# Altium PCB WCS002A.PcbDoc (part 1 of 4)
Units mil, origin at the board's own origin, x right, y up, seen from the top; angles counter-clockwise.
Board outline 2300 x 4058 mil, 4 copper layers (TOP, GND, PWR, BOTTOM), stack 28.8 mil thick; 311 components, 217 nets, 982 pads, 644 vias.
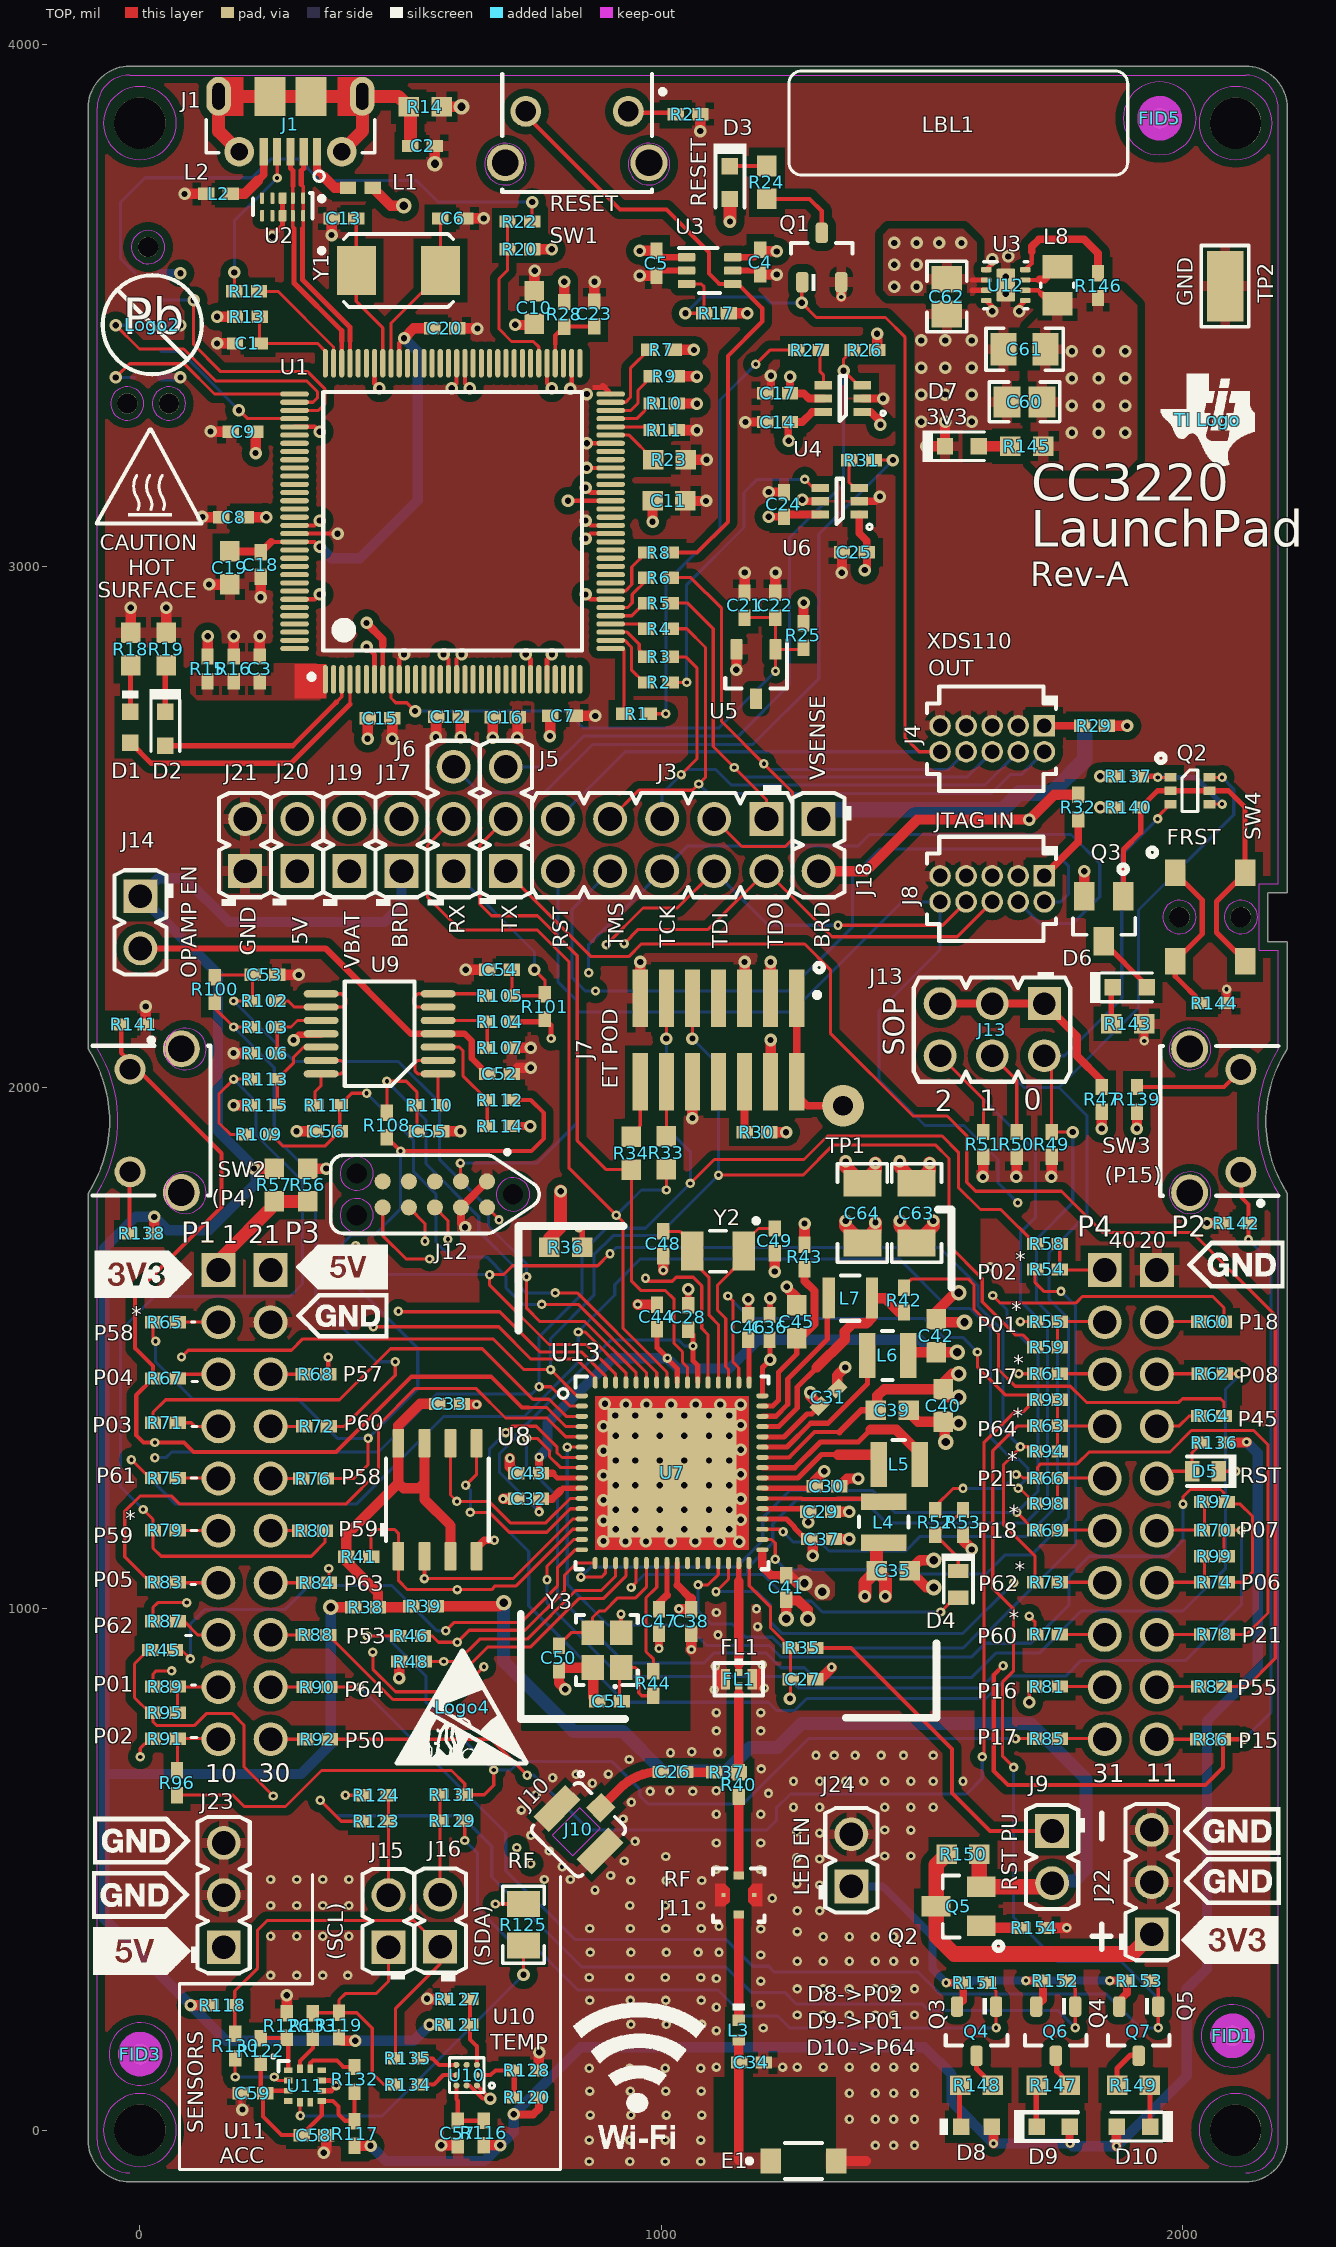
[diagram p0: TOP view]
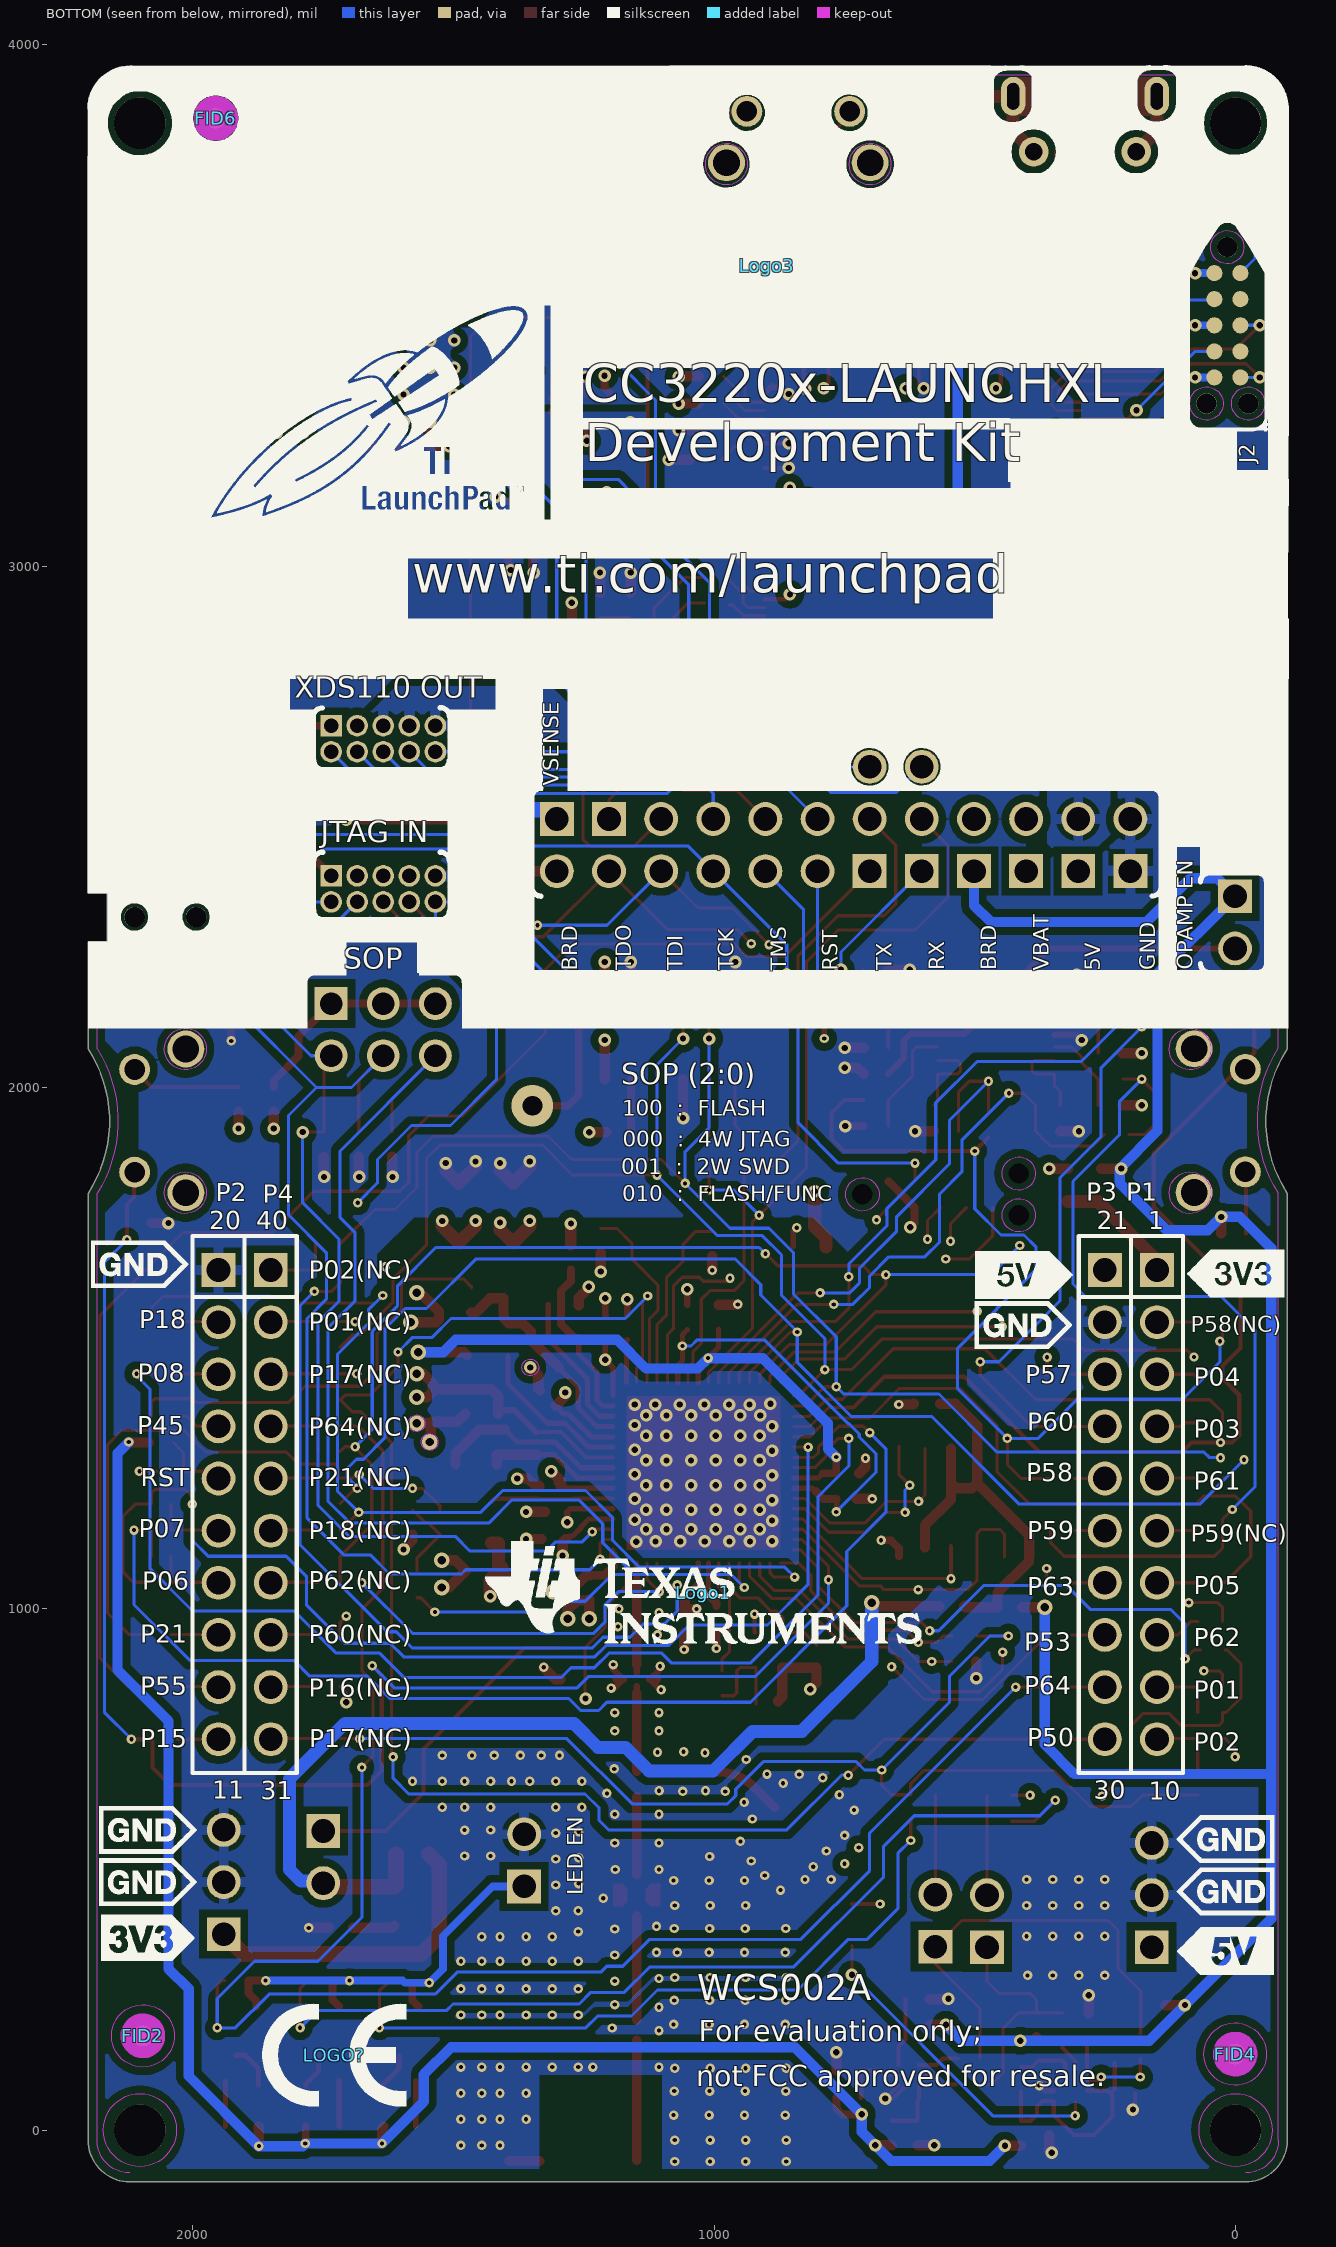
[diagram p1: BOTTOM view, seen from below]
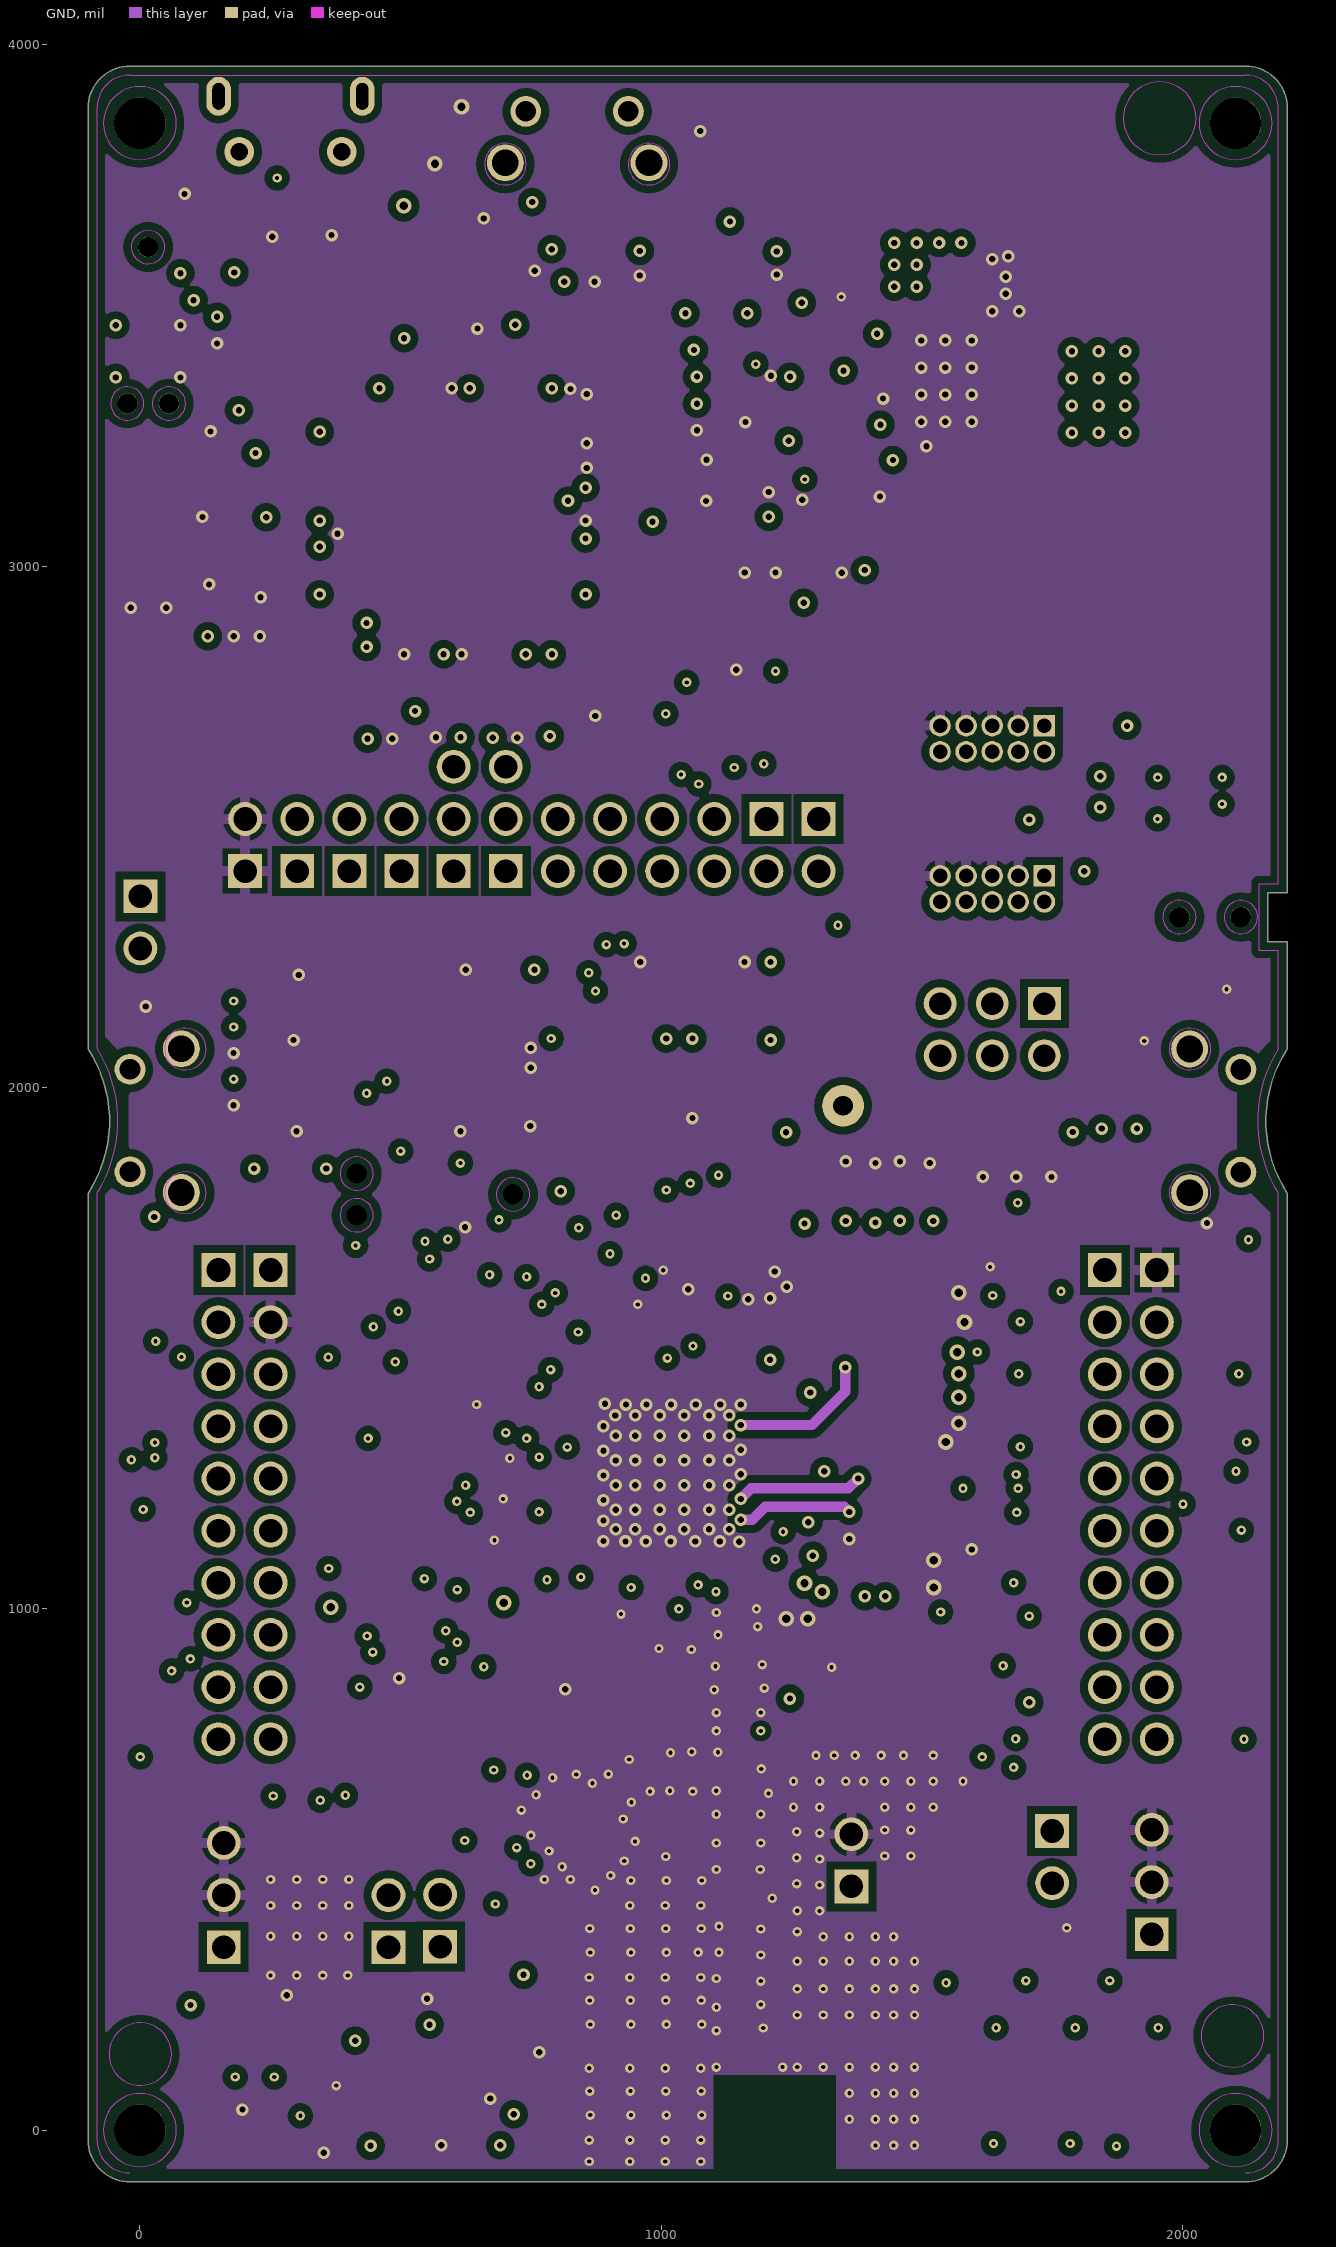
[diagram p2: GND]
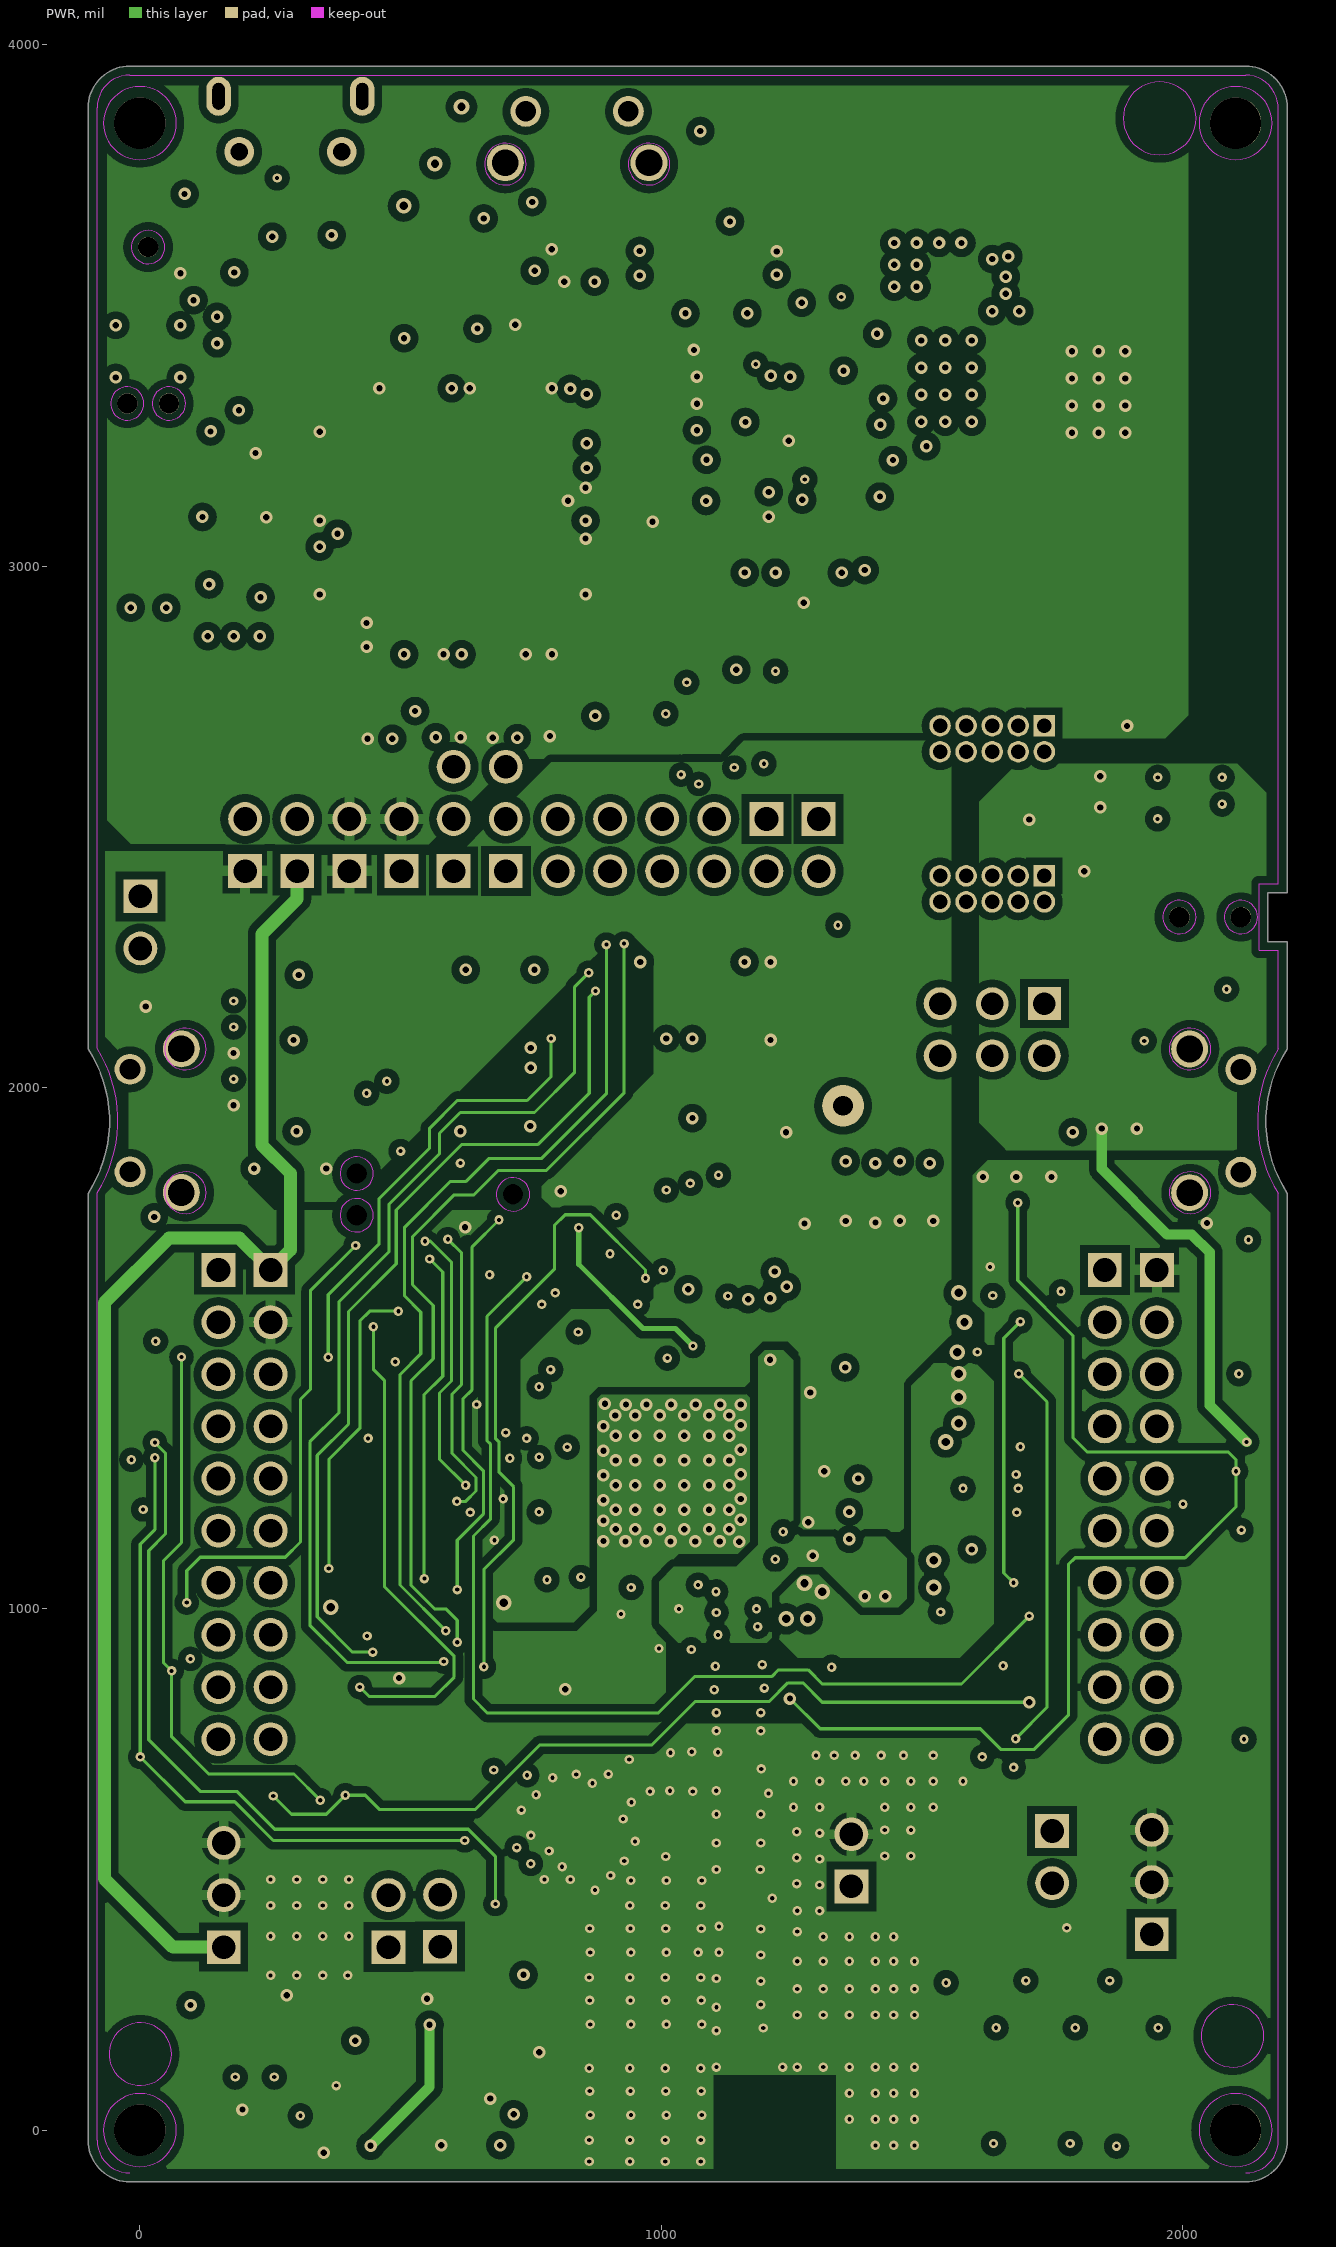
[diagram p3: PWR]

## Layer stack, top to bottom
Top Solder: solder mask 0.4, Solder Resist, Dk 3.5
TOP: signal copper 1.2
Dielectric1: core 8, FR-4, Dk 4.5
GND: signal copper 1.2
Dielectric2: prepreg 8, FR-4, Dk 4.5
PWR: signal copper 1.2
Dielectric3: core 8, FR-4, Dk 4.5
BOTTOM: signal copper 1.2
Bottom Solder: solder mask 0.4, Solder Resist, Dk 3.5

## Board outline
-99.21,-19.21 ccw(c-19.21,-19.21) -19.21,-99.21 2120.79,-99.21 ccw(c2120.79,-19.21) 2200.79,-19.21 2200.79,1796.79 cw(c2414.03,1935.38) 2200.79,2073.97 2200.79,2279.79 2163.79,2279.79 2163.79,2373.79 2200.79,2373.79 2200.79,3878.79 ccw(c2120.79,3878.79) 2120.79,3958.79 -19.21,3958.79 ccw(c-19.21,3878.79) -99.21,3878.79 -99.21,2073.97 cw(c-312.46,1935.38) -99.21,1796.79

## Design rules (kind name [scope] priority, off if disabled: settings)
Clearance Clearance_8 [InPadClass('u1') vs istrack] p1: gap=5.9
Clearance Clearance_7 [InPadClass('u1') vs InPadClass('u1')] p2: gap=5.9
Clearance Clearance_6 [InNet('NetC49_2') vs InPolygon] p3: gap=15
Clearance Clearance_5 [InNet('NetC49_1') vs InPolygon] p4: gap=15
Clearance Clearance_4 [InNet('NetFL1_3') vs InPolygon] p5: gap=15
Clearance Clearance_3 [InNet('NetFL1_1') vs InPolygon] p6: gap=15
Clearance Clearance_2 [InNet('NetJ24_2') vs InPolygon] p7: gap=15
Clearance Clearance_PAD [IsPad vs IsVia] p8: gap=6
Clearance Clearance_net1 [InNet('NetJ24_1') vs InPolygon] p9: gap=15
Clearance Clearance_Pad_class [InPadClass('Pad To Pad') vs IsPad] p10: gap=7.7
Clearance Clearance_Poly_Poly [InPolygon vs InPolygon] p11: gap=15
Clearance Clearance_Poly_Others [InPolygon] p12: gap=15
Clearance Clearance_1 [iskeepout vs OnLayer('M1  Board Outline')] p13: gap=20
Clearance Clearance_9 [InNet('XDSET_DP') vs InNet('XDSET_DM')] p14: gap=6
Clearance [All] p15: gap=0.9
DiffPairsRouting [All] p1: maxlimit=10 minlimit=6 mostfreqgap=6 toplayer_minwidth=8 toplayer_maxwidth=15 toplayer_prefwidth=10 midlayer1_minwidth=8 midlayer1_maxwidth=15 midlayer1_prefwidth=10 midlayer2_minwidth=8 midlayer2_maxwidth=15 midlayer2_prefwidth=10 bottomlayer_minwidth=8 bottomlayer_maxwidth=15 bottomlayer_prefwidth=10 maxuncoupledlength=500
MinimumSolderMaskSliver [All] p1: minsoldermaskwidth=4
PlaneClearance [All] p1: clearance=8
PlaneConnect PlaneConnect_1 [All] p1: planeconnectstyle=Direct reliefexpansion=20 reliefentries=4 reliefconductorwidth=10 reliefairgap=10
PolygonConnect PolygonConnect_1 [isvia] p1: connectstyle=Direct reliefconductorwidth=10 reliefentries=4 polygonreliefangle="90 Angle" airgapwidth=10
PolygonConnect [(InPadClass('direct connect'))] p2: connectstyle=Direct reliefconductorwidth=10 reliefentries=4 polygonreliefangle="90 Angle" airgapwidth=10
PolygonConnect PolygonConnect_SMD [All] p3: connectstyle=Relief reliefconductorwidth=20 reliefentries=4 polygonreliefangle="90 Angle" airgapwidth=10
RoutingVias [All] p1: holewidth=8 width=18 viastyle="Through Hole" minholewidth=8 minwidth=18 maxholewidth=28 maxwidth=50
SilkToSilkClearance SilkToSilkClearance_pb-logo [(HasFootprint('Pb-Free_Overlay_Medium') OR HasFootprint('Pb-Free_Overlay_Small')) vs (HasFootprint('Pb-Free_Overlay_Medium') OR HasFootprint('Pb-Free_Overlay_Small'))] p1: silktosilkclearance=0
SilkToSilkClearance [All] p2: silktosilkclearance=0
SilkToSolderMaskClearance [IsPad] p1: minsilkscreentomaskgap=0.1 clearancetoexposedcopper=FALSE
SilkToSolderMaskClearance SilkscreenOverComponentPads [IsPad] p2: minsilkscreentomaskgap=3 clearancetoexposedcopper=TRUE
SolderMaskExpansion SolderMaskExpansion_1 [InPadClass('MAsk')] p1: expansion=0.9
SolderMaskExpansion [All] p2: expansion=2
Width [All] p1: maxlimit=100 minlimit=6 preferedwidth=10
24 further rules are at their usual default settings.

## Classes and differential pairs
pad class MAsk: U1-1 U1-2 U1-3 U1-4 U1-5 U1-6 U1-7 U1-8 U1-9 U1-10 U1-11 U1-12 U1-13 U1-14 U1-15 U1-16 U1-17 U1-18 U1-19 U1-20 U1-21 U1-22 U1-23 U1-24 U1-25 U1-26 U1-27 U1-28 U1-29 U1-30 U1-31 U1-32 U1-33 U1-34 U1-35 U1-36 U1-37 U1-38 U1-39 U1-40 U1-41 U1-42 U1-43 U1-44 U1-45 U1-46 U1-47 U1-48 U1-49 U1-50 U1-51 U1-52 U1-53 U1-54 U1-55 U1-56 U1-57 U1-58 U1-59 U1-60 U1-61 U1-62 U1-63 U1-64 U1-65 U1-66 U1-67 U1-68 U1-69 U1-70 U1-71 U1-72 U1-73 U1-74 U1-75 U1-76 U1-77 U1-78 U1-79 U1-80 U1-81 U1-82 U1-83 U1-84 U1-85 U1-86 U1-87 U1-88 U1-89 U1-90 U1-91 U1-92 U1-93 U1-94 U1-95 U1-96 U1-97 U1-98 U1-99 U1-100 U1-101 U1-102 U1-103 U1-104 U1-105 U1-106 U1-107 U1-108 U1-109 U1-110 U1-111 U1-112 U1-113 U1-114 U1-115 U1-116 U1-117 U1-118 U1-119 U1-120 U1-121 U1-122 U1-123 U1-124 U1-125 U1-126 U1-127 U1-128
pad class "direct connect": C50-1 E1-1 E1-2 FL1-2 FL1-4 J18-1 J18-2 J18-3
component class FiducialMark: FID1 FID2 FID3 FID4 FID5 FID6
pad class "Pad To Pad": U6-A1 U6-A2 U6-A3 U6-B1 U6-B3 U6-C1 U6-C2 U6-C3
component class WCS002A_EngineArea: C26 C27 C28 C29 C30 C31 C32 C33 C34 C35 C36 C37 C38 C39 C40 C41 C42 C43 C44 C45 C46 C47 C48 C49 C50 C51 D4 E1 FL1 J9 J10 J11 J12 J13 L3 L4 L5 L6 L7 R35 R36 R37 R38 R39 R40 R41 R42 R43 R44 R45 R46 R47 R48 R49 R50 R51 R52 R53 U7 U8 Y2 Y3
component class WCS002A_HostInterface_ADC: C52 C53 C54 C55 C56 J14 P1 P2 P3 P4 R54 R55 R56 R57 R58 R59 R60 R61 R62 R63 R64 R65 R66 R67 R68 R69 R70 R71 R72 R73 R74 R75 R76 R77 R78 R79 R80 R81 R82 R83 R84 R85 R86 R87 R88 R89 R90 R91 R92 R93 R94 R95 R96 R97 R98 R99 R100 R101 R102 R103 R104 R105 R106 R107 R108 R109 R110 R111 R112 R113 R114 R115 U9
component class WCS002A_EmulationCircuit: C1 C2 C3 C4 C5 C6 C7 C8 C9 C10 C11 C12 C13 C14 C15 C16 C17 C18 C19 C20 C21 C22 C23 C24 C25 D1 D2 D3 J1 J2 J3 J4 J5 J6 J7 J8 L1 L2 Q1 R1 R2 R3 R4 R5 R6 R7 R8 R9 R10 R11 R12 R13 R14 R15 R16 R17 R18 R19 R20 R21 R22 R23 R24 R25 R26 R27 R28 R29 R30 R31 R32 R33 R34 SW1 TP1 U1 U2 U3 U4 U5 U6 Y1
component class WCS002A_PowerLedsSwitchSensors: C57 C58 C59 C60 C61 C62 C63 C64 D5 D6 D7 D8 D9 D10 J15 J16 J17 J18 J19 J20 J21 J22 J23 J24 L8 Q2 Q3 Q4 Q5 Q6 Q7 R116 R117 R118 R119 R120 R121 R122 R123 R124 R125 R126 R127 R128 R129 R130 R131 R132 R133 R134 R135 R136 R137 R138 R139 R140 R141 R142 R143 R144 R145 R146 R147 R148 R149 R150 R151 R152 R153 R154 SW2 SW3 SW4 TP2 U10 U11 U12
component class AssemblyNote: ZZ1 ZZ2 ZZ3 ZZ4
component class WCS002A_EVM_Hardware: FID1 FID2 FID3 FID4 FID5 FID6 LBL1 Logo1 Logo2 Logo3 Logo4 LOGO? "TI Logo" ZZ1 ZZ2 ZZ3 ZZ4
component class Header: J3 J5 J6 J7 J9 J13 J14 J15 J16 J17 J18 J19 J20 J21 J22 J23 J24
component class Label: LBL1
component class Logo: Logo1 "TI Logo"
pad class u1: U1-1 U1-2 U1-3 U1-4 U1-5 U1-6 U1-7 U1-8 U1-9 U1-10 U1-11 U1-12 U1-13 U1-14 U1-15 U1-16 U1-17 U1-18 U1-19 U1-20 U1-21 U1-22 U1-23 U1-24 U1-25 U1-26 U1-27 U1-28 U1-29 U1-30 U1-31 U1-32 U1-33 U1-34 U1-35 U1-36 U1-37 U1-38 U1-39 U1-40 U1-41 U1-42 U1-43 U1-44 U1-45 U1-46 U1-47 U1-48 U1-49 U1-50 U1-51 U1-52 U1-53 U1-54 U1-55 U1-56 U1-57 U1-58 U1-59 U1-60 U1-61 U1-62 U1-63 U1-64 U1-65 U1-66 U1-67 U1-68 U1-69 U1-70 U1-71 U1-72 U1-73 U1-74 U1-75 U1-76 U1-77 U1-78 U1-79 U1-80 U1-81 U1-82 U1-83 U1-84 U1-85 U1-86 U1-87 U1-88 U1-89 U1-90 U1-91 U1-92 U1-93 U1-94 U1-95 U1-96 U1-97 U1-98 U1-99 U1-100 U1-101 U1-102 U1-103 U1-104 U1-105 U1-106 U1-107 U1-108 U1-109 U1-110 U1-111 U1-112 U1-113 U1-114 U1-115 U1-116 U1-117 U1-118 U1-119 U1-120 U1-121 U1-122 U1-123 U1-124 U1-125 U1-126 U1-127 U1-128 U2-1 U2-2 U2-3 U2-4 U2-5 U2-6 U2-7 U2-8 U2-9 U2-10

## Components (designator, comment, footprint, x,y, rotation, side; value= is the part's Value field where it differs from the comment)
C1 "C1005X5R1A104K050BA" 0402#1 206,3427 r180 top
C2 "C1005X7R1C103K" 0402#1 542.28,3805.79 r0 top
C3 "C1005X7R1C103K" 0402#1 229.79,2802.79 r90 top
C4 "C1005X5R1A104K050BA" 0402#1 1189.79,3582.79 r270 top
C5 "C1005X5R1A104K050BA" 0402#1 990.79,3580.79 r270 top
C6 "GRM1555C1H220FA01D" 0402#1 600.12,3666.7 r180 top
C7 "C1005X7R1C103K" 0402#1 810.79,2712.79 r0 top
C8 "C1005X7R1C103K" 0402#1 179.79,3093.79 r180 top
C9 "C1005X7R1C103K" 0402#1 198.17,3257.79 r180 top
C10 "06033D104KAT2A" 0603 756.79,3495.79 r90 top
C11 "06033D104KAT2A" 0603 1014.79,3124.79 r0 top
C12 "C1005X5R1C105K050BC" 0402#1 591.79,2710.79 r180 top
C13 "GRM1555C1H220FA01D" 0402#1 391.37,3666.61 r0 top
C14 "C1005X5R1A104K050BA" 0402#1 1223.39,3276.2 r180 top
C15 "C1005X7R1C103K" 0402#1 460.79,2707.79 r0 top
C16 "C1005X5R1C105K050BC" 0402#1 700.79,2709.79 r0 top
C17 "C1005X5R1A104K050BA" 0402#1 1223.39,3331.2 r180 top
C18 "C1005X5R1C225K050BC" 0402#1 231.79,3002.79 r270 top
C19 "06033D104KAT2A" 0603 172.79,2996.79 r270 top
C20 "C1005X5R1C105K050BC" 0402#1 584.79,3455.79 r0 top
C21 "C1005X7R1C103K" 0402#1 1159.79,2924.79 r90 top
C22 "C1005X5R1C105K050BC" 0402#1 1218.79,2924.79 r90 top
C23 "C1005X5R1C105K050BC" 0402#1 871.79,3483.79 r90 top
C24 "C1005X5R1A104K050BA" 0402#1 1235.39,3118.2 r90 top
C25 "C1005X5R1A104K050BA" 0402#1 1370.39,3026.2 r180 top
C26 "GRM1555C1H100JA01D" 0402#1 1022.41,687.05 r180 top
C27 "GRM155R61A105KE15D" 0402#1 1271.79,864.79 r0 top
C28 "C1005X5R1A104K050BA" 0402#1 1051.79,1558.79 r90 top
C29 "C1005X5R0J475M050BC" 0402#1 1305.79,1185.79 r0 top
C30 "C1005X5R0J475M050BC" 0402#1 1317.79,1234.79 r0 top
C31 "C1005X5R0J475M050BC" 0402#1 1320.79,1405.79 r45 top
C32 "C1005X5R1A104K050BA" 0402#1 745.79,1210.79 r180 top
C33 "C1005X5R1A104K050BA" 0402#1 593.66,1392.89 r0 top
C34 "GJM1555C1HR50BB01J" 0402#1 1172.88,129.79 r180 top
C35 "GRM188R60J106ME47D" 0603 1444.79,1072.79 r0 top
C36 "C1005X5R1A104K050BA" 0402#1 1207.79,1539.79 r90 top
C37 "C1005X5R1A104K050BA" 0402#1 1307.79,1133.79 r0 top
C38 "C1005X5R1A104K050BA" 0402#1 1057.79,975.79 r270 top
C39 "C1608X5R0G226M080AA" 0603 1442.79,1380.79 r0 top
C40 "C1608X5R0G226M080AA" 0603 1540.79,1389.79 r270 top
C41 "C1005X5R1A105K050BB" 0402#1 1239.79,1040.79 r270 top
C42 "GRM188R60J106ME47D" 0603 1527.79,1523.79 r90 top
C43 "C1005X5R1A104K050BA" 0402#1 745.79,1259.79 r180 top
C44 "C1005X5R1A104K050BA" 0402#1 991.79,1559.79 r90 top
C45 "GRM188R60J106ME47D" 0603 1259.79,1550.79 r90 top
C46 "C1005X5R1A104K050BA" 0402#1 1166.79,1539.79 r90 top
C47 "C1005X5R1A104K050BA" 0402#1 995.79,975.79 r270 top
C48 "GRM1555C1H100JA01D" 0402#1 1003.79,1700.12 r270 top
C49 "GRM1555C1H100JA01D" 0402#1 1217.79,1705.79 r270 top
C50 "GRM1555C1H6R2CA01D" 0402#1 803.79,905.79 r270 top
C51 "GRM1555C1H6R2CA01D" 0402#1 900.79,822.79 r180 top
C52 "GRM155R61A103KA01D" 0402#1 689.79,2025.79 r0 top
C53 "C1005X7R1C103K" 0402#1 239.79,2215.79 r0 top
C54 "C1005X7R1C103K" 0402#1 689.79,2225.79 r180 top
C55 "C1005X7R1C103K" 0402#1 554.79,1915.79 r0 top
C56 "C1005X7R1C103K" 0402#1 359.79,1915.79 r180 top
C57 "C1005X5R1A104K050BA" 0402#1 609.79,-5.59 r270 top
C58 "C1005X5R1A104K050BA" 0402#1 333.79,-9.59 r0 top
C59 "C1005X5R1A104K050BA" 0402#1 216.79,70.41 r180 top
C60 "GRM21BR61A106KE19L" 0805 1696.79,3314.79 r180 top locked
C61 "C2012X5R1C226K125AC" 0805_HV 1696.79,3415.79 r180 top locked
C62 "GRM21BR61A106KE19L" 0805 1547.79,3516.79 r270 top
C63 "GRM31CR60J107ME39L" 1206 1489.79,1758.79 r90 top
C64 "GRM31CR60J107ME39L" 1206 1385.79,1758.79 r90 top
D1 "SML-LX0603GW-TR" LED_SML-LX0603GW -18.21,2690.79 r90 top
D2 "SML-311UTT86" SML-31_Red 48.79,2687.79 r270 top locked
D3 "150060YS75000" WL-SMCW_YELLOW 1131.79,3735.49 r270 top
D4 "CD0603-B00340" Diode_0603 1569.79,1046.79 r270 top
D5 "CD0603-B00340" Diode_0603 2043.79,1263.79 r180 top
D6 "SML-311UTT86" SML-31_Red 1898.79,2191.79 r0 top
D7 "SML-311UTT86" SML-31_Red 1576.79,3229.79 r0 top
D8 "SML-LX0603GW-TR" LED_SML-LX0603GW 1604.79,6.79 r180 top
D9 "150060YS75000" WL-SMCW_YELLOW 1751.79,6.79 r0 top
D10 "SML-311UTT86" SML-31_Red 1905.79,6.79 r180 top
E1 "AH316M245001-T" TAYO_AH316M 1272.6,-59.21 r0 top
FID1 "Fiducial" Fiducial10-20 2095.79,180.79 r90 top
FID2 "Fiducial" Fiducial10-20 2095.79,180.79 r90 bottom
FID3 "Fiducial" Fiducial10-20 0.79,145.79 r90 top
FID4 "Fiducial" Fiducial10-20 0.79,145.79 r90 bottom
FID5 "Fiducial" Fiducial10-20 1956.1,3858.79 r90 top
FID6 "Fiducial" Fiducial10-20 1956.1,3858.79 r90 bottom
FL1 "DEA202450BT-1294C1-H" TDK_DEA202450BT-1294C1-H 1148.74,864.79 r0 top
J1 "105017-0001" CONN_105017-0001 288.79,3847.79 r180 top locked
J2 "TC2050-IDC-NL-FP" Tag_TC2050-NL 15.79,3461.79 r180 bottom
J3 "61301021121" WURTH_61301021121 1001.79,2464.79 r180 top locked
J4 "FTSH-105-01-F-D-K" Samtec_FTSH-105-01-x-D-K 1634.79,2668.79 r270 top
J5 "61300311121" WURTH_61300311121 701.79,2514.79 r90 top locked
J6 "61300311121" WURTH_61300311121 601.79,2514.79 r90 top locked
J7 "FTSH-107-01-F-DV" Samtec_FTSH-107-01-x-DV 1109.79,2090.79 r270 top locked
J8 "FTSH-105-01-F-D-K" Samtec_FTSH-105-01-x-D-K 1634.79,2380.79 r270 top
J9 "61300211121" WURTH_61300211121 1749.79,523.79 r270 top
J10 "U.FL-R-SMT-1" CONN_UFL-R-SMT-1 841.3,576.25 r225 top locked
J11 "MM8030-2610RJ3" MURATA_MM8030-2610 1148.79,450.79 r270 top
J12 "TC2050-IDC-430-FP" TC2050-IDC-430-FP 565.79,1794.79 r270 top locked
J13 "61300621121" Wurth_61300621121 1634.79,2110.79 r270 top locked
J14 "61300211121" WURTH_61300211121 1,2316.5 r270 top
J15 "61300211121" WURTH_61300211121 476.79,400.79 r90 top locked
J16 "61300211121" WURTH_61300211121 575.79,401.79 r90 top locked
J17 "61300211121" WURTH_61300211121 501.79,2464.79 r90 top locked
J18 "61300211121" WURTH_61300211121 1301.79,2464.79 r270 top
J19 "61300211121" WURTH_61300211121 401.79,2464.79 r90 top locked
J20 "61300211121" WURTH_61300211121 301.79,2464.79 r90 top locked
J21 "61300211121" WURTH_61300211121 201.79,2464.79 r90 top locked
J22 "61300311121" WURTH_61300311121 1940.79,475.79 r90 top locked
J23 "61300311121" WURTH_61300311121 160.79,450.79 r90 top locked
J24 "61300211121" WURTH_61300211121 1364.6,517.5 r90 top
L1 "BLM15AG100SN1D" 0402#1 422.79,3725.79 r0 top
L2 "BLM15AG100SN1D" 0402#1 150.79,3713.79 r180 top
L3 "LQG15HS3N3S02D" IND_LQG15H 1148.74,191.79 r270 top
L4 "LQM2HPN2R2MG0L" 1008 1426.79,1165.79 r90 top locked
L5 "LQM2HPN1R0MG0L" 1008 1456.79,1276.79 r180 top
L6 "LQM2HPN2R2MG0L" 1008 1434.79,1485.79 r180 top locked
L7 "CBC2518T100M" CBC2518 1362.79,1595.79 r0 top
L8 "BRC2012T2R2MD" 0805_140 1759.79,3538.79 r270 top
LBL1 "Size: 0.65\" x 0.20 \"" Label_650x200 1569.79,3849.79 r180 top
Logo1 "Texas Instruments" TI_Stacked_Overlay_Small 1020.8,1031.1 r180 bottom
Logo2 "Pb-Free Symbol" Pb-Free_Overlay_Medium 23.8,3462.9 r0 top
Logo3 "FCC disclaimer" FCC_disclaimer 898.79,3575.79 r180 bottom
Logo4 "ESD Susceptible" ESD_Overlay_Medium 618,811 r0 top
LOGO? "CE Mark" CE_Mark_5mm 1728.9,143.9 r180 bottom
P1 "SSW-110-23-F-S" CONN_SSW-110-23-F-S 150.7,1199.79 r90 bottom locked (schematic designator P3)
P2 "SSW-110-23-F-S" CONN_SSW-110-23-F-S 1950.7,1199.78 r90 bottom locked
P3 "SSW-110-23-F-S" CONN_SSW-110-23-F-S 250.7,1199.79 r90 bottom locked (schematic designator P4)
P4 "SSW-110-23-F-S" CONN_SSW-110-23-F-S 1850.7,1199.78 r90 bottom locked (schematic designator P1)
Q1 "BSS138" SOT-23 1307.79,3591.79 r90 top locked
Q2 "BSS84DW-7-F" SOT-363 2014.09,2568.99 r0 top
Q3 "FDN358P" SSOT-3 1848.99,2323.51 r180 top
Q4 "BSS138" SOT-23 1604.79,189.79 r270 top
Q5 "FDN358P" SSOT-3 1570.48,429.39 r90 top
Q6 "BSS138" SOT-23 1756.79,189.79 r270 top
Q7 "BSS138" SOT-23 1915.79,189.79 r270 top
R1 "ERJ-2RKF33R0X" 0402#1 952.79,2716.79 r180 top
R2 "ERJ-2RKF33R0X" 0402#1 994.79,2776.79 r180 top
R3 "ERJ-2RKF33R0X" 0402#1 994.79,2825.79 r180 top
R4 "ERJ-2RKF33R0X" 0402#1 994.79,2879.79 r180 top
R5 "ERJ-2RKF33R0X" 0402#1 994.79,2928.79 r180 top
R6 "ERJ-2RKF33R0X" 0402#1 994.79,2977.79 r180 top
R7 "CRCW04021K00JNED" 0402#1 1000.17,3414.79 r180 top
R8 "ERJ-2RKF33R0X" 0402#1 994.79,3025.79 r180 top
R9 "CRCW04021K00JNED" 0402#1 1005.79,3363.79 r180 top
R10 "CRCW04021K00JNED" 0402#1 1005.79,3311.79 r180 top
R11 "CRCW04021K00JNED" 0402#1 1005.79,3260.79 r180 top
R12 "ERJ-2GE0R00X" 0402#1 204.79,3526.79 r0 top
R13 "CRCW0402100RJNED" 0402#1 206,3478 r0 top
R14 "CRCW0603100KJNEA" 0603 547.28,3880.79 r180 top
R15 "CRCW0402330KJNED" 0402#1 129.79,2802.79 r270 top
R16 "CRCW0402220KJNED" 0402#1 179.79,2802.79 r270 top
R17 "CRCW0402100KJNED" 0402#1 1105.79,3484.79 r0 top
R18 "CRCW0603220RJNEA" 0603 -17.21,2840.79 r270 top
R19 "CRCW0603220RJNEA" 0603 50.79,2840.79 r270 top
R20 "CRCW040210K0JNED" 0402#1 728.79,3607.79 r180 top
R21 "ERJ-2RKF1000X" 0402#1 1051.41,3866.79 r180 top
R22 "CRCW0402100RFKED" 0402#1 728.79,3660.79 r180 top
R23 "CRCW06034K87FKEA" 0603 1015.79,3203.79 r180 top
R24 "CRCW0603270RJNEA" 0603 1202.79,3735.79 r90 top
R25 "CRCW04021K00JNED" 0402#1 1272.79,2866.79 r90 top
R26 "CRCW0402100KJNED" 0402#1 1390.39,3414.2 r180 top
R27 "ERJ-2RKF33R0X" 0402#1 1282.39,3414.2 r180 top
R28 "CRCW040251R0JNED" 0402#1 813.79,3482.79 r270 top
R29 "CRCW04021K00JNED" 0402#1 1830.79,2693.79 r180 top
R30 "CRCW04021K00JNED" 0402#1 1183.41,1914.17 r0 top
R31 "ERJ-2RKF33R0X" 0402#1 1384.39,3203.2 r180 top
R32 "CRCW04021K00JNED" 0402#1 1799.91,2537.79 r270 top
R33 "CRCW060333R0JNEA" 0603 1009.79,1874.79 r90 top
R34 "CRCW060333R0JNEA" 0603 942.79,1873.79 r90 top
R35 "CRCW040210K0JNED" 0402#1 1271.79,924.79 r180 top
R36 "ERJ-3GEY0R00V" 0603 816.79,1693.79 r180 top
R37 "ERJ-2GE0R00X" 0402#1 1125.17,686.41 r180 top
R38 "ERJ-2GE0R00X" 0402#1 433.09,1002.79 r180 top
R39 "ERJ-2GE0R00X" 0402#2 567.79,1004.79 r0 top
R40 "ERJ-2GE0R00X" 0402#1 1148.79,662.79 r270 top
R41 "CRCW0402100KJNED" 0402#1 419.79,1099.79 r0 top
R42 "ERJ-2GE0R00X" 0402#1 1465.79,1591.79 r90 top
R43 "ERJ-2GE0R00X" 0402#1 1274.79,1674.79 r90 top
R44 "ERJ-2GE0R00X" 0402#1 984.79,856.79 r90 top
R45 "ERJ-2GE0R00X" 0402#1 43.79,920.79 r180 top
R46 "ERJ-2GE0R00X" 0402#1 519.41,947.79 r180 top
R47 "CRCW0402270RJNED" 0402#1 1844.8,1977.17 r90 top
R48 "CRCW0402100KJNED" 0402#1 520.79,898.79 r180 top
R49 "CRCW0402100KJNED" 0402#1 1748.79,1890.79 r270 top
R50 "CRCW0402100KJNED" 0402#1 1681.79,1890.79 r270 top
R51 "CRCW0402100KJNED" 0402#1 1617.79,1890.79 r270 top
R52 "CRCW04022K20JNED" 0402#1 1525.79,1165.79 r90 top
R53 "CRCW040210K0JNED" 0402#1 1578.79,1165.79 r270 top
R54 "ERJ-2GE0R00X" 0402#1 1740.79,1650.79 r0 top
R55 "ERJ-2GE0R00X" 0402#1 1740.79,1550.79 r0 top
R56 "ERJ-3GEY0R00V" 0603 321.79,1812.79 r270 top
R57 "ERJ-3GEY0R00V" 0603 257.79,1812.79 r270 top
R58 "ERJ-2GE0R00X" 0402#1 1740.79,1699.79 r0 top
R59 "ERJ-2GE0R00X" 0402#1 1740.79,1501.79 r0 top
R60 "ERJ-2GE0R00X" 0402#1 2055.79,1550.79 r0 top
R61 "ERJ-2GE0R00X" 0402#1 1740.79,1450.79 r0 top
R62 "ERJ-2GE0R00X" 0402#1 2056.87,1450.79 r0 top
R63 "ERJ-2GE0R00X" 0402#1 1740.79,1350.79 r0 top
R64 "ERJ-2GE0R00X" 0402#1 2055.79,1369.79 r0 top
R65 "ERJ-2GE0R00X" 0402#1 48.79,1549.79 r0 top
R66 "ERJ-2GE0R00X" 0402#1 1740.79,1250.79 r0 top
R67 "ERJ-2GE0R00X" 0402#1 48.79,1441.79 r0 top
R68 "ERJ-2GE0R00X" 0402#1 337.79,1449.79 r0 top
R69 "ERJ-2GE0R00X" 0402#1 1740.79,1150.79 r0 top
R70 "ERJ-2GE0R00X" 0402#1 2060.79,1150.79 r0 top
R71 "ERJ-2GE0R00X" 0402#1 48.79,1356.79 r0 top
R72 "ERJ-2GE0R00X" 0402#1 338.79,1349.79 r0 top
R73 "ERJ-2GE0R00X" 0402#1 1740.79,1050.79 r0 top
R74 "ERJ-2GE0R00X" 0402#1 2060.79,1050.79 r0 top
R75 "ERJ-2GE0R00X" 0402#1 48.79,1250.79 r0 top
R76 "ERJ-2GE0R00X" 0402#1 332.9,1249.8 r0 top
R77 "ERJ-2GE0R00X" 0402#1 1740.79,950.79 r0 top
R78 "ERJ-2GE0R00X" 0402#1 2060.79,950.79 r0 top
R79 "ERJ-2GE0R00X" 0402#1 48.79,1150.79 r0 top
R80 "ERJ-2GE0R00X" 0402#1 331.5,1149.9 r0 top
R81 "ERJ-2GE0R00X" 0402#1 1740.79,850.79 r0 top
R82 "ERJ-2GE0R00X" 0402#1 2055.79,850.79 r0 top
R83 "ERJ-2GE0R00X" 0402#1 48.79,1050.79 r0 top
R84 "ERJ-2GE0R00X" 0402#1 338.79,1049.79 r0 top
R85 "ERJ-2GE0R00X" 0402#1 1740.79,750.79 r0 top
R86 "ERJ-2GE0R00X" 0402#1 2053.79,749.78 r0 top
R87 "ERJ-2GE0R00X" 0402#1 48.79,975.79 r0 top
R88 "ERJ-2GE0R00X" 0402#1 337.79,949.79 r0 top
R89 "ERJ-2GE0R00X" 0402#1 48.79,850.79 r0 top
R90 "ERJ-2GE0R00X" 0402#1 339.79,849.79 r0 top
R91 "ERJ-2GE0R00X" 0402#1 48.79,750.79 r0 top
R92 "ERJ-2GE0R00X" 0402#1 340.79,749.79 r0 top
R93 "ERJ-2GE0R00X" 0402#1 1740.79,1400.79 r0 top
R94 "ERJ-2GE0R00X" 0402#1 1740.79,1301.79 r0 top
R95 "ERJ-2GE0R00X" 0402#1 48.79,800.79 r0 top
R96 "ERJ-2GE0R00X" 0402#1 71.19,666.3 r90 top
R97 "ERJ-2GE0R00X" 0402#1 2060.79,1204.79 r0 top
R98 "ERJ-2GE0R00X" 0402#1 1740.79,1201.79 r0 top
R99 "ERJ-2GE0R00X" 0402#1 2060.79,1100.79 r0 top
R100 "ERJ-2GE0R00X" 0402#1 143.79,2187.79 r90 top
R101 "ERJ-2GE0R00X" 0402#1 776.79,2154.79 r90 top
R102 "ERJ-2RKF4700X" 0402#1 239.79,2165.79 r180 top
R103 "CRCW0402576KFKED" 0402#1 239.79,2115.79 r0 top
R104 "CRCW0402576KFKED" 0402#1 689.79,2125.79 r180 top
R105 "ERJ-2RKF4700X" 0402#1 689.79,2175.79 r0 top
R106 "CRCW0402422KFKED" 0402#1 239.79,2065.79 r0 top
R107 "CRCW0402422KFKED" 0402#1 689.79,2075.79 r180 top
R108 "ERJ-2GE0R00X" 0402#1 473.79,1927.79 r90 top
R109 "ERJ-2GE0R00X" 0402#1 227.79,1909.79 r0 top
R110 "ERJ-2RKF4700X" 0402#1 554.79,1965.79 r180 top
R111 "ERJ-2RKF4700X" 0402#1 359.79,1965.79 r0 top
R112 "CRCW0402576KFKED" 0402#1 689.79,1975.79 r180 top
R113 "CRCW0402576KFKED" 0402#1 239.79,2015.79 r0 top
R114 "CRCW0402422KFKED" 0402#1 689.79,1925.79 r180 top
R115 "CRCW0402422KFKED" 0402#1 239.79,1965.79 r0 top
R116 "ERJ-2GE0R00X" 0402#1 659.31,-5.28 r270 top
R117 "ERJ-2GE0R00X" 0402#1 411.79,-6.59 r270 top
R118 "CRCW04023K30JNED" 0402#1 158.27,239.79 r0 top
R119 "CRCW04023K30JNED" 0402#1 381.79,201.41 r90 top
R120 "ERJ-2GE0R00X" 0402#1 741.79,62.62 r0 top
R121 "ERJ-2GE0R00X" 0402#1 609.71,202.14 r180 top
R122 "ERJ-2GE0R00X" 0402#1 231.79,152.41 r270 top
R123 "ERJ-2GE0R00X" 0402#1 453.17,592.31 r0 top
R124 "ERJ-2GE0R00X" 0402#1 453.17,642.31 r0 top
R125 "ERJ-6GEY0R00V" 0805_HV 735.79,393.79 r90 top
R126 "ERJ-2GE0R00X" 0402#1 281.79,200.41 r270 top
R127 "ERJ-2GE0R00X" 0402#1 609.79,251.41 r0 top
R128 "ERJ-2GE0R00X" 0402#1 741.79,114.41 r180 top
R129 "ERJ-2GE0R00X" 0402#1 599.41,593.31 r180 top
R130 "ERJ-2GE0R00X" 0402#1 182.79,161.41 r270 top
R131 "ERJ-2GE0R00X" 0402#1 599.41,643.31 r180 top
R132 "ERJ-2GE0R00X" 0402#1 411.79,97.41 r270 top
R133 "ERJ-2GE0R00X" 0402#1 331.79,200.41 r270 top
R134 "ERJ-2GE0R00X" 0402#1 513.79,87.41 r0 top
R135 "ERJ-2GE0R00X" 0402#1 514.05,137.62 r0 top
R136 "CRCW0402100KJNED" 0402#1 2060.79,1318.79 r180 top
R137 "CRCW04021K00JNED" 0402#1 1896.09,2596.99 r180 top
R138 "CRCW04021K00JNED" 0402#1 3.79,1719.79 r180 top
R139 "CRCW04021K00JNED" 0402#1 1912.41,1977.17 r90 top
R140 "ERJ-2RKF1003X" 0402#1 1896.09,2536.99 r180 top
R141 "CRCW040210K0JNED" 0402#1 -12.21,2120.79 r0 top
R142 "CRCW040210K0JNED" 0402#1 2102.79,1739.79 r180 top
R143 "CRCW0603270RJNEA" 0603 1894.79,2121.79 r180 top
R144 "CRCW04021K00JNED" 0402#1 2060.79,2161.79 r180 top
R145 "CRCW0603270RJNEA" 0603 1701.29,3229.79 r180 top
R146 "CRCW0402100KJNED" 0402#1 1837.79,3537.79 r270 top
R147 "CRCW0603270RJNEA" 0603 1751.79,85.79 r180 top
R148 "CRCW0603270RJNEA" 0603 1604.79,85.79 r180 top
R149 "CRCW0603270RJNEA" 0603 1905.79,85.79 r0 top
R150 "ERJ-3GEY0R00V" 0603 1578.79,528.79 r0 top
R151 "CRCW0402100KJNED" 0402#1 1602.79,282.79 r180 top
R152 "CRCW0402100KJNED" 0402#1 1755.79,286.79 r180 top
R153 "CRCW0402100KJNED" 0402#1 1916.79,286.79 r180 top
R154 "ERJ-2GE0R00X" 0402#1 1715.79,387.79 r180 top
SW1 "MJTP1117" SW_MJTP1117 838.7,3949.5 r180 top
SW2 "MJTP1117" SW_MJTP1117 -96.5,1936.2 r270 top
SW3 "MJTP1117" SW_MJTP1117 2189.4,1935.9 r90 top
SW4 "EVQ-PSD02K" SW_EVQ-PSD02K 2052.79,2326.79 r0 top locked
"TI Logo" "Texas Instruments" TI_Symbol_Overlay_Small 2048,3280.2 r0 top
TP1 "TESTPOINT" TESTPOINT 1348.79,1964.79 r270 top
TP2 "5015" Testpoint_Keystone_Miniature 2081.79,3536.79 r270 top
U1 "TM4C1294NCPDTI3R" PDT0128A_N 599.79,3085.79 r90 top locked
U2 "TPD4S010DQAR" DQA0010A 273.79,3688.79 r270 top
U3 "SN74LVC1T45DCKR" DCK0006A_N#1 1092.79,3566.79 r0 top
U4 "SN74LVC1T45DCKR" DCK0006A_N#2 1348.39,3321.2 r180 top
U5 "LM4040B25IDBZR" DBZ0003A_N 1181.79,2792.79 r270 top
U6 "SN74LVC1T45DCKR" DCK0006A_N#2 1342.39,3124.2 r180 top
U7 "CC3220SF12ARGKR" RGK0064B 1020.79,1260.79 r0 top locked
U8 "MX25R3235FM1IL0" SOP-8_150MIL 570.79,1209.01 r90 top
U9 "OPA4342EA/250" PW0014A_N 459.79,2102.79 r180 top locked
U10 "TMP006AIYZF" YZF0008AEAE 626.79,105.41 r180 top locked
U11 "BMA222E" 12LGA 316.79,85.41 r0 top
U12 "TPS62162DSGR" DSG0008A 1660.79,3538.79 r0 top
Y1 "ABM3-16.000MHZ-D2Y-T" XTAL_ABM3 495.79,3566.79 r0 top
Y2 "ABS07-32.768KHZ-9-T" XTAL_ABS07 1108.79,1685.79 r180 top
Y3 "Q24FA20H0039600" Epson_FA-20H 895.79,920.79 r180 top
ZZ1 "This Assembly Note is for PCB labels only" AssemblyNoteLabel -890,5774.8 r0 top
ZZ2 "These assemblies are ESD sensitive, ESD precautions shall be observed." AssemblyNote -890,5681.1 r0 top
ZZ3 "These assemblies must be clean and free from flux and all contaminants. Use of no clean flux is not acceptable." AssemblyNote -889.6,5578.3 r0 top
ZZ4 "These assemblies must comply with workmanship standards IPC-A-610 Class 2, unless otherwise specified." AssemblyNote -893.1,5481.3 r0 top

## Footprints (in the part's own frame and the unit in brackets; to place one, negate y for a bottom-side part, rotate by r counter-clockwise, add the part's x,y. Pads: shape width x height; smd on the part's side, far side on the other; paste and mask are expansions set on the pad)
12LGA [mm] "LGA, 12-Leads, Body 2x2mm, Pitch 0.5mm"
  rect 0.41x0.28 smd: 1(-0.815,0.75) 2(-0.815,0.25) 3(-0.815,-0.25) 4(-0.815,-0.75) 7(0.815,-0.75) 8(0.815,-0.25) 9(0.815,0.25) 10(0.815,0.75)
  rect 0.28x0.41 smd: 5(-0.25,-0.815) 6(0.25,-0.815) 11(0.25,0.815) 12(-0.25,0.815)
  silkscreen extent -1.3,0.7 -0.8,1.2, body extent -1.04,-1.04 1.04,1.04, height 1.01
0402#1 [mm] "0402 from SM-752 data"
  rect 0.8x0.6 smd: 1(-0.6,0) 2(0.6,0)
  body extent -0.55,-0.3 0.55,0.3, height 0.6
0402#2 [mm] "0402 from SM-752 data"
  rect 0.8x0.6 smd: 1(-1.2,0) 2(0,0)
  body extent -1.15,-0.3 0.55,0.3, height 0.6
0603 [mm] "0603 from SM-752 data"
  rect 1x0.95 smd: 1(-0.8,0) 2(0.8,0)
  body extent -0.87,-0.47 0.87,0.47, height 1
0805 [mm] "0805 from SM-752 data"
  rect 1.3x1.5 smd: 1(-0.85,0) 2(0.85,0)
  silkscreen extent -1.72,-0.97 1.72,0.97, body extent -1.1,-0.72 1.1,0.72, height 1.1
0805_140 [mm] "0805 / 1.4mm height"
  rect 1.15x1.45 smd: 1(-0.9,0) 2(0.9,0)
  silkscreen extent -0.1,-0.8 0.1,0.8, body extent -1.1,-0.72 1.1,0.72, height 1.4
0805_HV [mil] "0805 with 30mil clearance between pads"
  rect 50x63 smd: 1(-40,0) 2(40,0)
  silkscreen extent -74,-40 74,40, body extent -43,-29 43,29, height 57
1008 [mm] "SMD, Body 2.5x2mm, Height 1.2mm"
  rect 0.8x2.2 smd: 1(-1,0) 2(1,0)
  silkscreen extent -0.25,-1.2 0.27,1.2, body extent -1.35,-1.1 1.35,1.1, height 1.2
1206 [mm] "1206 from SM-752 data"
  rect 1.3x1.85 smd: 1(-1.45,0) 2(1.45,0)
  silkscreen extent -2.4,-1.21 2.4,1.21, body extent -1.7,-0.9 1.7,0.9, height 1.35
AssemblyNote [mil] "Assembly Note"
AssemblyNoteLabel [mil] "Assembly Note for PCB Labels"
CBC2518 [mm] "Taiyo Yuden"
  rect 0.6x2 smd: 1(-1.05,0) 2(1.05,0)
  silkscreen extent -0.45,-1.1 0.45,1.1, body extent -1.35,-1 1.35,1, height 2
CE_Mark_5mm [mil] "Minimum text height for CE Mark"
  silkscreen extent -138,-98 138,98
CONN_105017-0001 [mm] "Molex Micro USB-B"
  rect 0.4x1.35 smd mask+0.051: 1(-1.3,1.35) 2(-0.65,1.35) 3(0,1.35) 4(0.65,1.35) 5(1.3,1.35)
  oval 1.2x1.9 hole 0.6 slot 1.3 at 90 deg: 6(-3.5,-1.35) 9(3.5,-1.35)
  rect 1.5x1.9 smd: 7(-1,-1.35) 8(1,-1.35)
  round 1.45 hole 0.85: 10(2.5,1.35) 11(-2.5,1.35)
  TOP region: -3.499,-2.3 -2.299,-2.3 -2.299,-0.4 -3.499,-0.4
  TOP region: 3.499,-0.4 2.299,-0.4 2.299,-2.3 3.499,-2.3
  silkscreen extent -4.1,-0.2 4.1,2.79, body extent -4.1,-3.93 4.1,1.5, height 2.72
CONN_SSW-110-23-F-S [mm] "SAMTEC"
  rect 1.65x1.65 hole 1.15: 1(11.43,0)
  round 1.65 hole 1.15: 2(8.89,0) 3(6.35,0) 4(3.81,0) 5(1.27,0) 6(-1.27,0) 7(-3.81,0) 8(-6.35,0) 9(-8.89,0) 10(-11.43,0)
  silkscreen extent -13.08,-1.27 13.08,1.27, body extent -13,-1.27 13,1.27, height 8.59
CONN_UFL-R-SMT-1 [mm] "Hirose recommended land pattern http://www.hirose.co.jp/cataloge_hp/e32119372.pdf 2009.2"
  rect 1.05x1 smd: 1(-1.525,0)
  rect 2.2x1.05 smd: 2(0,1.475) 3(0,-1.475)
  TOP keep-out region: -0.8,-0.7 1.1,-0.7 1.1,0.7 -0.8,0.7
  silkscreen extent -1.7,-1.7 1.7,1.7, body extent -1.55,-1.5 1.55,1.5, height 1.27
DBZ0003A_N [mm] "SOT23, 3-Leads, Body 2.9x1.3mm, Pitch 0.95mm, Lead Span 2.4mm, IPC Medium Density"
  rrect17% 1x0.6 smd: 1(-1.2,0.95) 2(-1.2,-0.95) 3(1.2,0)
  silkscreen extent -1.65,-1.5 0.7,1.5, body extent -1.26,-1.46 1.26,1.46, height 0.98
DCK0006A_N#1 [mm] "SOT23, 6-Leads, Body 2x1.3mm, Pitch 0.65mm, Lead Span 2.1mm, IPC Medium Density"
  rrect25% 0.85x0.4 smd: 1(-1.125,0.65) 2(-1.125,0) 3(-1.125,-0.65) 4(1.125,-0.65) 5(1.125,0) 6(1.125,0.65)
  silkscreen extent -1.5,-1.09 0.51,1.09, body extent -1.14,-1 1.14,1, height 0.95
DCK0006A_N#2 [mm] "SOT23, 6-Leads, Body 2x1.3mm, Pitch 0.65mm, Lead Span 2.1mm, IPC Medium Density"
  rect 0.85x0.4 smd: 1(-0.95,0.65) 2(-0.95,0) 3(-0.95,-0.65) 4(0.95,-0.65) 5(0.95,0) 6(0.95,0.65)
  silkscreen extent -0.15,-1.1 0.15,1.1, body extent -1.14,-1 1.14,1, height 0.94
Diode_0603 [mm] "Based on Bourns recommended land pattern Rev 10/09"
  rect 0.7x1 smd: 1(-0.65,0) 2(0.65,0)
  silkscreen extent -1.5,-0.8 0.9,0.8, body extent -0.9,-0.5 0.9,0.5, height 0.85
DQA0010A [mm] "SON, 10-Leads, Body 1x2.5mm, Pitch 0.5mm, TI Recommended"
  rrect50% 0.55x0.2 smd: 1(-0.425,1) 2(-0.425,0.5) 4(-0.425,-0.5) 5(-0.425,-1) 6(0.425,-1) 7(0.425,-0.5) 9(0.425,0.5) 10(0.425,1)
  rrect25% 0.55x0.4 smd mask+0.038: 3(-0.425,0) 8(0.425,0)
  silkscreen extent -0.67,-1.45 0.55,1.45, body extent -0.55,-1.3 0.55,1.3, height 0.56
DSG0008A [mm] "SON, 8-Leads, Body 2x2mm, Pitch 0.5mm, Thermal Pad 1.6x0.9mm, TI Recommended"
  rrect40% 0.5x0.25 smd: 1(-0.95,0.75) 2(-0.95,0.25) 3(-0.95,-0.25) 4(-0.95,-0.75) 5(0.95,-0.75) 6(0.95,-0.25) 7(0.95,0.25) 8(0.95,0.75)
  rrect11% 0.9x1.6 smd paste-0.45: 9(0,0)
  silkscreen extent -1.07,-1.15 1.07,1.15, body extent -1.05,-1.05 1.05,1.05, height 0.8
Epson_FA-20H [mm] "SMD, 4-Leads, Body 2.5x2mm"
  rect 1.1x1.2 smd: 1(-0.7,0.85) 2(-0.7,-0.85) 3(0.7,-0.85) 4(0.7,0.85)
  silkscreen extent -1.5,-1.7 1.5,1.7, body extent -1.05,-1.3 1.05,1.3, height 0.56
ESD_Overlay_Medium [mil]
  silkscreen extent -127,-109 125,110
FCC_disclaimer [mil]
Fiducial10-20 [mm]
  round 1 smd mask+0.5: 1(0,0)
  TOP keep-out circle w1.178: c0,0 r0.5
IND_LQG15H [mm] "MuRata"
  rect 0.55x0.6 smd: 1(-0.475,0) 2(0.475,0)
  silkscreen extent -1.3,-0.3 -0.95,0.3, body extent -0.52,-0.27 0.52,0.27, height 0.55
Label_650x200 [mil] "Thermal Transfer Label"
  round 1 on Mech13: 0(0,0)
  silkscreen extent -325,-100 325,100, body extent -325,-100 325,100, height 1
LED_SML-LX0603GW [mm] "LUMEX OPTO"
  rect 0.8x0.8 smd: 1(-0.75,0) 2(0.75,0)
  silkscreen extent 1.4,-0.4 1.8,0.4, body extent -0.8,-0.4 0.8,0.4, height 0.6
MURATA_MM8030-2610 [mm] "Coaxial Connectors with Switch, SMD"
  rect 0.4x0.5 smd paste-0.5: 1(-0.95,0) 2(0.95,0)
  rect 0.2x0.2 smd paste-0.2: 3(0,0.75) 4(0,-0.75)
  TOP region: -0.32,-0.45 -0.55,-0.68 -0.55,-1.15 0.55,-1.15 0.55,-0.68 0.32,-0.45
  TOP region: -0.32,0.45 -0.55,0.68 -0.55,1.15 0.55,1.15 0.55,0.68 0.32,0.45
  silkscreen extent -1.3,-1.25 1.3,1.25, body extent -1.15,-1.1 1.15,1.1, height 1
Pb-Free_Overlay_Medium [mil]
  silkscreen extent -95,-95 95,95
PDT0128A_N [mm] "Thin QFP, 128-Leads, Body 14x14mm, Pitch 0.4mm, IPC Medium Density"
  oval 1.4x0.25 smd: 1(-7.7,6.2) 2(-7.7,5.8) 3(-7.7,5.4) 4(-7.7,5) 5(-7.7,4.6) 6(-7.7,4.2) 7(-7.7,3.8) 8(-7.7,3.4) 9(-7.7,3) 10(-7.7,2.6) 11(-7.7,2.2) 12(-7.7,1.8) 13(-7.7,1.4) 14(-7.7,1) 15(-7.7,0.6) 16(-7.7,0.2) 17(-7.7,-0.2) 18(-7.7,-0.6) 19(-7.7,-1) 20(-7.7,-1.4) 21(-7.7,-1.8) 22(-7.7,-2.2) 23(-7.7,-2.6) 24(-7.7,-3) 25(-7.7,-3.4) 26(-7.7,-3.8) 27(-7.7,-4.2) 28(-7.7,-4.6) 29(-7.7,-5) 30(-7.7,-5.4) 31(-7.7,-5.8) 32(-7.7,-6.2) 65(7.7,-6.2) 66(7.7,-5.8) 67(7.7,-5.4) 68(7.7,-5) 69(7.7,-4.6) 70(7.7,-4.2) 71(7.7,-3.8) 72(7.7,-3.4) 73(7.7,-3) 74(7.7,-2.6) 75(7.7,-2.2) 76(7.7,-1.8) 77(7.7,-1.4) 78(7.7,-1) 79(7.7,-0.6) 80(7.7,-0.2) 81(7.7,0.2) 82(7.7,0.6) 83(7.7,1) 84(7.7,1.4) 85(7.7,1.8) 86(7.7,2.2) 87(7.7,2.6) 88(7.7,3) 89(7.7,3.4) 90(7.7,3.8) 91(7.7,4.2) 92(7.7,4.6) 93(7.7,5) 94(7.7,5.4) 95(7.7,5.8) 96(7.7,6.2)
  oval 0.25x1.4 smd: 33(-6.2,-7.7) 34(-5.8,-7.7) 35(-5.4,-7.7) 36(-5,-7.7) 37(-4.6,-7.7) 38(-4.2,-7.7) 39(-3.8,-7.7) 40(-3.4,-7.7) 41(-3,-7.7) 42(-2.6,-7.7) 43(-2.2,-7.7) 44(-1.8,-7.7) 45(-1.4,-7.7) 46(-1,-7.7) 47(-0.6,-7.7) 48(-0.2,-7.7) 49(0.2,-7.7) 50(0.6,-7.7) 51(1,-7.7) 52(1.4,-7.7) 53(1.8,-7.7) 54(2.2,-7.7) 55(2.6,-7.7) 56(3,-7.7) 57(3.4,-7.7) 58(3.8,-7.7) 59(4.2,-7.7) 60(4.6,-7.7) 61(5,-7.7) 62(5.4,-7.7) 63(5.8,-7.7) 64(6.2,-7.7) 97(6.2,7.7) 98(5.8,7.7) 99(5.4,7.7) 100(5,7.7) 101(4.6,7.7) 102(4.2,7.7) 103(3.8,7.7) 104(3.4,7.7) 105(3,7.7) 106(2.6,7.7) 107(2.2,7.7) 108(1.8,7.7) 109(1.4,7.7) 110(1,7.7) 111(0.6,7.7) 112(0.2,7.7) 113(-0.2,7.7) 114(-0.6,7.7) 115(-1,7.7) 116(-1.4,7.7) 117(-1.8,7.7) 118(-2.2,7.7) 119(-2.6,7.7) 120(-3,7.7) 121(-3.4,7.7) 122(-3.8,7.7) 123(-4.2,7.7) 124(-4.6,7.7) 125(-5,7.7) 126(-5.4,7.7) 127(-5.8,7.7) 128(-6.2,7.7)
  silkscreen extent -7.7,-6.3 6.3,6.99, body extent -8,-8 8,8, height 1.07
PW0014A_N [mm] "TSOP, 14-Leads, Body 5x4.4mm, Pitch 0.65mm, IPC Medium Density"
  oval 1.7x0.35 smd: 1(-2.85,1.95) 2(-2.85,1.3) 3(-2.85,0.65) 4(-2.85,0) 5(-2.85,-0.65) 6(-2.85,-1.3) 7(-2.85,-1.95) 8(2.85,-1.95) 9(2.85,-1.3) 10(2.85,-0.65) 11(2.85,0) 12(2.85,0.65) 13(2.85,1.3) 14(2.85,1.95)
  silkscreen extent -1.7,-2.55 1.7,2.55, body extent -3.21,-2.5 3.21,2.5, height 0.98
RGK0064B [mm] "QFN, 9.0x9.0"
  rrect100% 0.6x0.24 smd: 1(-4.4,3.75) 2(-4.4,3.25) 3(-4.4,2.75) 4(-4.4,2.25) 5(-4.4,1.75) 6(-4.4,1.25) 7(-4.4,0.75) 8(-4.4,0.25) 9(-4.4,-0.25) 10(-4.4,-0.75) 11(-4.4,-1.25) 12(-4.4,-1.75) 13(-4.4,-2.25) 14(-4.4,-2.75) 15(-4.4,-3.25) 16(-4.4,-3.75) 33(4.4,-3.75) 34(4.4,-3.25) 35(4.4,-2.75) 36(4.4,-2.25) 37(4.4,-1.75) 38(4.4,-1.25) 39(4.4,-0.75) 40(4.4,-0.25) 41(4.4,0.25) 42(4.4,0.75) 43(4.4,1.25) 44(4.4,1.75) 45(4.4,2.25) 46(4.4,2.75) 47(4.4,3.25) 48(4.4,3.75)
  rrect100% 0.24x0.6 smd: 17(-3.75,-4.4) 18(-3.25,-4.4) 19(-2.75,-4.4) 20(-2.25,-4.4) 21(-1.75,-4.4) 22(-1.25,-4.4) 23(-0.75,-4.4) 24(-0.25,-4.4) 25(0.25,-4.4) 26(0.75,-4.4) 27(1.25,-4.4) 28(1.75,-4.4) 29(2.25,-4.4) 30(2.75,-4.4) 31(3.25,-4.4) 32(3.75,-4.4) 49(3.75,4.4) 50(3.25,4.4) 51(2.75,4.4) 52(2.25,4.4) 53(1.75,4.4) 54(1.25,4.4) 55(0.75,4.4) 56(0.25,4.4) 57(-0.25,4.4) 58(-0.75,4.4) 59(-1.25,4.4) 60(-1.75,4.4) 61(-2.25,4.4) 62(-2.75,4.4) 63(-3.25,4.4) 64(-3.75,4.4)
  rrect2% 6.3x6.3 smd paste-4: 65(0,0)
  silkscreen extent -4.7,-4.7 4.7,4.7, body extent -4.57,-4.57 4.57,4.57, height 1.02
Samtec_FTSH-105-01-x-D-K [mm] "Header, 1.27 mm, 5x2, TH"
  rect 1.05x1.05 hole 0.71: 1(-0.635,2.54)
  round 1.05 hole 0.71: 2(0.635,2.54) 3(-0.635,1.27) 4(0.635,1.27) 5(-0.635,0) 6(0.635,0) 7(-0.635,-1.27) 8(0.635,-1.27) 9(-0.635,-2.54) 10(0.635,-2.54)
  silkscreen extent -2.54,-3.17 2.54,3.2, body extent -2.54,-3.17 2.54,3.1, height 5.73
Samtec_FTSH-107-01-x-DV [mm] "Header, 1.27mm, 7x2, SMT"
  rect 2.79x0.74 smd: 1(-2.035,3.81) 2(2.035,3.81) 3(-2.035,2.54) 4(2.035,2.54) 5(-2.035,1.27) 6(2.035,1.27) 7(-2.035,0) 8(2.035,0) 9(-2.035,-1.27) 10(2.035,-1.27) 11(-2.035,-2.54) 12(2.035,-2.54) 13(-2.035,-3.81) 14(2.035,-3.81)
  silkscreen extent -2.32,4.68 -2.08,4.93, body extent -2.94,-4.48 2.9,4.41, height 5.97
SML-31_Red [mm] "Rohm"
  rect 0.8x0.8 smd: 1(-0.825,0) 2(0.825,0)
  silkscreen extent -1.93,-0.76 1.1,0.76, body extent -0.85,-0.45 0.85,0.45, height 0.91
SOP-8_150MIL [mm] "SOP, 8-Leads, Body 5.03x4mm, Pitch 1.27mm"
  rrect18% 1.4x0.57 smd: 1(-2.75,1.905) 2(-2.75,0.635) 3(-2.75,-0.635) 4(-2.75,-1.905) 5(2.75,-1.905) 6(2.75,-0.635) 7(2.75,0.635) 8(2.75,1.905)
  silkscreen extent -2,-2.5 2,2.79, body extent -2,-2.5 2,2.5, height 1.76
SOT-23 [mm] "SOT23, 3-Leads, Body 2.9x1.3mm, Pitch 0.95mm, Lead Span 2.5mm, IPC Medium Density"
  rrect50% 1x0.6 smd: 1(-1.2,0.95) 2(-1.2,-0.95) 3(1.2,0)
  silkscreen extent -1.62,-1.5 0.7,1.5, body extent -1.16,-1.45 1.21,1.45, height 1
SOT-363 [mm]
  rect 0.6x0.42 smd mask+0.051: 1(-0.95,0.65) 2(-0.95,0) 3(-0.95,-0.65) 4(0.95,-0.65) 5(0.95,0) 6(0.95,0.65)
  silkscreen extent -0.38,-1.02 0.38,1.02, body extent -1.1,-1.1 1.1,1.1, height 1.12
SSOT-3 [mm] "SuperSOT-3"
  rect 1x1.4 smd: 1(-0.95,-1.1) 2(0.95,-1.1) 3(0,1.1)
  silkscreen extent -1.53,-0.05 1.5,0.77, body extent -1.52,-0.76 1.52,0.76, height 1.12
SW_EVQ-PSD02K [mm] "Panasonic"
  rect 1x1.3 smd: 1(-1.7,2.15) 2(-1.7,-2.15) 3(1.7,-2.15) 4(1.7,2.15)
  round 1 hole 1 unplated mask+0.127: MH1(-1.5,0) MH2(1.5,0)
  body extent -3.05,-2.3 4.35,2.3, height 1.8
SW_MJTP1117 [mm] "TH, 2-Leads, Body 7.3x5.9mm, Pitch 5mm"
  round 1.5 hole 1: 1(-2.5,1.97) 2(2.5,1.97)
  round 1.8 hole 1.3: MH1(-3.5,4.47) MH2(3.5,4.47)
  silkscreen extent -3.65,0.15 3.65,5.9, body extent -3.95,-1.45 3.95,5.9, height 4.3
Tag_TC2050-NL [mil] "Footprint for Tag-Connect TC2050 No-Legs cables"
  round 31 smd paste-15.75: 1(-25,100) 2(-25,50) 3(-25,0) 4(-25,-50) 5(-25,-100) 6(25,-100) 7(25,-50) 8(25,0) 9(25,50) 10(25,100)
  round 39 hole 39 unplated mask+5: MH1(0,150) MH2(-40,-150) MH3(40,-150)
  silkscreen extent -75,-200 75,200
TAYO_AH316M [mm] "SMD, 2-Leads, Body 3.2x1.6mm"
  rect 1x1.2 smd: 1(-1.6,0) 2(1.6,0)
  silkscreen extent -2.73,-0.87 0.9,0.87, body extent -1.68,-0.87 1.68,0.87, height 0.61
TC2050-IDC-430-FP [mil] "TAG-CONNECT"
  round 31 smd paste-16: 1(-25,100) 2(-25,50) 3(-25,0) 4(-25,-50) 5(-25,-100) 6(25,-100) 7(25,-50) 8(25,0) 9(25,50) 10(25,100)
  round 31 hole 39 unplated mask+10: MH1(0,150) MH2(-40,-150) MH3(40,-150)
  silkscreen extent -75,-200 75,200
TDK_DEA202450BT-1294C1-H [mm] "SMD, 4-Leads, Body 2x1.25mm"
  rect 0.35x0.35 smd: 1(0,0.325) 3(0,-0.325)
  rect 0.45x1 smd paste-1.27: 2(0.65,0) 4(-0.65,0)
  silkscreen extent -1.17,-0.8 1.17,1, body extent -1.07,-0.67 1.07,0.67, height 0.8
TESTPOINT [mil]
  round 80 hole 37.99: 1(0,0)
Testpoint_Keystone_Miniature [mil] "Miniature SMT test point"
  rect 135x70 smd: 1(0,0)
  silkscreen extent -78,-46 78,45, body extent -52,-20 52,20, height 61
TI_Stacked_Overlay_Small [mil]
  silkscreen extent -418,-98 418,98
TI_Symbol_Overlay_Small [mil]
  silkscreen extent -90,-88 91,88
WL-SMCW_YELLOW [mm] "WURTH"
  rect 0.8x0.8 smd: 1(-0.8,0) 2(0.8,0)
  silkscreen extent -1.9,-0.8 1.2,0.8, body extent -0.85,-0.45 0.85,0.45, height 0.8
WURTH_61300211121 [mm] "Header, 2.54mm, 2x1, TH"
  rect 1.65x1.65 hole 1.15: 1(-1.27,0)
  round 1.65 hole 1.15: 2(1.27,0)
  silkscreen extent -2.54,-1.27 2.54,1.6, body extent -2.54,-1.27 2.54,1.27, height 8.54
WURTH_61300311121 [mm] "Header, 2.54mm, 3x1, TH"
  rect 1.65x1.65 hole 1.15: 1(-2.54,0)
  round 1.65 hole 1.15: 2(0,0) 3(2.54,0)
  silkscreen extent -4.14,-1.27 3.81,1.27, body extent -3.81,-1.27 3.81,1.27, height 8.54
Wurth_61300621121 [mm] "Header, 2.54mm, 3x2, TH"
  rect 1.6x1.6 hole 1.1: 1(-1.27,2.54)
  round 1.6 hole 1.1: 2(1.27,2.54) 3(-1.27,0) 4(1.27,0) 5(-1.27,-2.54) 6(1.27,-2.54)
  silkscreen extent -2.8,-3.82 2.54,3.8, body extent -2.54,-3.82 2.54,3.8, height 7.27
WURTH_61301021121 [mm] "Header, 2.54mm, 5x2, TH"
  rect 1.65x1.65 hole 1.15: 1(-5.08,-1.27)
  round 1.65 hole 1.15: 2(-5.08,1.27) 3(-2.54,-1.27) 4(-2.54,1.27) 5(0,-1.27) 6(0,1.27) 7(2.54,-1.27) 8(2.54,1.27) 9(5.08,-1.27) 10(5.08,1.27)
  silkscreen extent -6.35,-2.92 6.35,2.54, body extent -6.35,-2.54 6.35,2.54, height 8.54
XTAL_ABM3 [mm] "Abracon recommended land pattern 12.28.10"
  rect 1.9x2.4 smd: 1(-2.05,0) 2(2.05,0)
  silkscreen extent -2.67,-1.78 2.67,1.78, body extent -2.6,-1.7 2.6,1.7, height 1.3
XTAL_ABS07 [mm] "ABRACON"
  rect 1.1x1.9 smd: 1(-1.25,0) 2(1.25,0)
  silkscreen extent -0.4,-1 0.4,1, body extent -1.65,-0.8 1.65,0.8, height 0.9
YZF0008AEAE [mm] "WCSP"
  round 0.3 smd paste-0.15 mask+0.04: A1(-0.5,0.5) A2(0,0.5) A3(0.5,0.5) B1(-0.5,0) B3(0.5,0) C1(-0.5,-0.5) C2(0,-0.5) C3(0.5,-0.5)
  silkscreen extent -1.35,-0.85 0.85,0.85, body extent -0.78,-0.78 0.78,0.78, height 0.63

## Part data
C1 C4 C5 C14 C17 C24 C25 C28 C32 C33 C36 C37 C38 C43 C44 C46 C47 C57 C58 C59: "CAP, CERM, 0.1 µF, 10 V, +/- 10%, X5R, 0402"
C2 C3 C7 C8 C9 C15 C21 C53 C54 C55 C56: "CAP, CERM, 0.01 µF, 16 V, +/- 10%, X7R, 0402"
C6 C13: "CAP, CERM, 22 pF, 50 V, +/- 1%, C0G/NP0, 0402"
C10 C11 C19: "CAP, CERM, 0.1 µF, 25 V, +/- 10%, X5R, 0603"
C12 C16 C20 C22 C23: "CAP, CERM, 1 µF, 16 V, +/- 10%, X5R, 0402"
C18: "CAP, CERM, 2.2 µF, 16 V, +/- 10%, X5R, 0402"
C26 C48 C49: "CAP, CERM, 10 pF, 50 V, +/- 5%, C0G/NP0, 0402"
C27 C41: "CAP, CERM, 1 µF, 10 V, +/- 10%, X5R, 0402"
C29 C30 C31: "CAP, CERM, 4.7 µF, 6.3 V, +/- 20%, X5R, 0402"
C34: library part GRM1555C1H1R0BA01D, "CAP, CERM, 0.5 pF, 50 V, +/- 10%, C0G/NP0, 0402"
C35 C42 C45: "CAP, CERM, 10 µF, 6.3 V, +/- 20%, X5R, 0603"
C39 C40: "CAP, CERM, 22 µF, 4 V, +/- 20%, X5R, 0603"
C50 C51: "CAP, CERM, 6.2 pF, 50 V, +/- 5%, C0G/NP0, 0402"
C52: "CAP, CERM, 0.01 µF, 10 V, +/- 10%, X5R, 0402"
C60 C62: "CAP, CERM, 10 µF, 10 V, +/- 10%, X5R, 0805"
C61: "CAP, CERM, 22 µF, 16 V, +/- 10%, X5R, 0805"
C63 C64: "CAP, CERM, 100 µF, 6.3 V, +/- 20%, X5R, 1206"
D1 D8: "LED, Green, SMD"
D2 D6 D7 D10: "LED, Red, SMD"
D3 D9: "LED, Yellow, SMD"
D4 D5: "Diode, Schottky, 45 V, 0.03 A, 0603 Diode"
E1: "ANT BLUETOOTH W-LAN ZIGBEE WIMAX, SMD"
FID1 FID2 FID3 FID4 FID5 FID6: "Fiducial mark.  There is nothing to buy or mount."
FL1: "Multilayer Chip Band Pass Filter For 2.4GHz W-LAN/Bluetooth, SMD"
J1: "Connector, Receptacle, Micro-USB Type B, R/A, Bottom Mount SMT"
J2: "Footprint for Tag-Connect TC2050 No-Legs cables"
J3: "Header, 2.54 mm, 5x2, Gold, TH"
J4 J8: "Header, 1.27 mm, 5x2, Gold, TH"
J5 J6 J22 J23: "Header, 2.54 mm, 3x1, Gold, TH"
J7: "Header, 1.27mm, 7x2, Gold, SMT"
J9 J14 J15 J16 J17 J18 J19 J20 J21 J24: "Header, 2.54 mm, 2x1, Gold, TH"
J10: "Connector, Ultra-Mini Coaxial, SMD"
J11: "Coaxial Connectors with Switch, 50 Ohm, SMD"
J12: "Footprint for TC2050-IDC-430"
J13: "Header, 2.54mm, 3x2, Gold, TH"
L1 L2: "Ferrite Bead, 10 ohm @ 100 MHz, 1 A, 0402"
L3: "Inductor, Multilayer, Air Core, 3.3 nH, 0.3 A, 0.17 ohm, SMD"
L4 L6: "Inductor, Multilayer, Ferrite, 2.2 µH, 1.3 A, 0.08 ohm, SMD"
L5: "Inductor, Multilayer, Ferrite, 1 µH, 1.6 A, 0.055 ohm, SMD"
L7: "Inductor, Wirewound, Ceramic, 10 µH, 0.48 A, 0.36 ohm, SMD"
L8: "Inductor, Wirewound, 2.2 µH, 1 A, 0.143 ohm, SMD"
LBL1: library part THT-14-423-10, "Thermal Transfer Printable Labels, 0.650\" W x 0.200\" H - 10,000 per roll"
Logo1 "TI Logo": library part TI_Logo, "Texas Instrument Corporate Signature"
Logo2: library part Pb-Free
Logo3: library part FCC_disclaimer, "FCC_disclaimer"
Logo4: library part ESD_Susceptible, "ESD Susceptible Symbol"
P1 P2 P3 P4: "Connector, Receptacle, 100mil, 10x1, Gold plated, TH"
Q1 Q4 Q6 Q7: "MOSFET, N-CH, 50 V, 0.22 A, SOT-23"
Q2: "MOSFET, P-CH, -50 V, -0.13 A, AEC-Q101, SOT-363"
Q3 Q5: "MOSFET, P-CH, -30 V, -1.5 A, SSOT-3"
R1 R2 R3 R4 R5 R6 R8 R27 R31: "RES, 33.0, 1%, 0.1 W, 0402"
R7 R9 R10 R11 R25 R29 R30 R32 R137 R138 R139 R144: "RES, 1.0 k, 5%, 0.063 W, 0402"
R12 R37 R38 R39 R40 R42 R43 R44 R45 R46 R54 R55 R58 R59 R60 R61 R62 R63 R64 R65 R66 R67 R68 R69 R70 R71 R72 R73 R74 R75 R76 R77 R78 R79 R80 R81 R82 R83 R84 R85 R86 R87 R88 R89 R90 R91 R92 R93 R94 R95 R96 R97 R98 R99 R100 R101 R108 R109 R116 R117 R120 R121 R122 R123 R124 R126 R127 R128 R129 R130 R131 R132 R133 R134 R135 R154: "RES, 0, 5%, 0.063 W, 0402"
R13: "RES, 100, 5%, 0.063 W, 0402"
R14: "RES, 100 k, 5%, 0.1 W, 0603"
R15: "RES, 330 k, 5%, 0.063 W, 0402"
R16: "RES, 220 k, 5%, 0.063 W, 0402"
R17 R26 R41 R48 R49 R50 R51 R136 R146 R151 R152 R153: "RES, 100 k, 5%, 0.063 W, 0402"
R18 R19: "RES, 220, 5%, 0.1 W, 0603"
R20 R35 R53 R141 R142: "RES, 10 k, 5%, 0.063 W, 0402"
R21: "RES, 100, 1%, 0.1 W, 0402"
R22: "RES, 100, 1%, 0.063 W, 0402"
R23: "RES, 4.87 k, 1%, 0.1 W, 0603"
R24 R143 R145 R147 R148 R149: "RES, 270, 5%, 0.1 W, 0603"
R28: "RES, 51, 5%, 0.063 W, 0402"
R33 R34: "RES, 33, 5%, 0.1 W, 0603"
R36 R56 R57 R150: "RES, 0, 5%, 0.1 W, 0603"
R47: "RES, 270, 5%, 0.063 W, 0402"
R52: "RES, 2.2 k, 5%, 0.063 W, 0402"
R102 R105 R110 R111: "RES, 470, 1%, 0.1 W, 0402"
R103 R104 R112 R113: "RES, 576 k, 1%, 0.063 W, 0402"
R106 R107 R114 R115: "RES, 422 k, 1%, 0.063 W, 0402"
R118 R119: "RES, 3.3 k, 5%, 0.063 W, 0402"
R125: "RES, 0, 5%, 0.125 W, 0805"
R140: "RES, 100 k, 1%, 0.1 W, 0402"
SW1 SW2 SW3: "Switch, SPST-NO, Off-Mom, 1 Pos, 0.05A, 12VDC, TH"
SW4: "Switch, Tactile, SPST-NO, SMT"
TP1: "TEST POINT.  No entry in BOM."
TP2: "Test Point, Miniature, SMT"
U1: "Tiva C Series Microcontroller, PDT0128A"
U2: "ESD Solution for High-Speed Differential Interface, 4 Channels, -40 to +85 degC,10-pin SON (DQA), Green (RoHS & no Sb/Br)"
U3 U4 U6: "Single-Bit Dual-Supply Bus Transceiver With Configurable Voltage Translation and 3-State Outputs, DCK0006A"
U5: "Precision Micropower Shunt Voltage Reference, 0.2% accuracy, 2.5 V, 15 ppm / degC, 15 mA, -40 to 85 degC, 3-pin SOT-23 (DBZ), Green (RoHS & no Sb/Br)"
U7: "SimpleLink Wi-Fi and Internet-of-Things Solution, a Single-Chip Wireless MCU, RGK0064B (VQFN-64)"
U8: "ULTRA LOW POWER, 32M-BIT [x 1/x 2/x 4] CMOS MXSMIO(SERIAL MULTI I/O) FLASH MEMORY, SOP-8"
U9: "Low Cost, Low Power, Rail-to-Rail Operational Amplifier MicroAmplifier(TM) Series, 2.7 to 5.5 V, -55 to 125 degC, 14-pin SOP (PW0014A), Green (RoHS & no Sb/Br)"
U10: "Infrared Thermopile Sensor in Chip-Scale Package, YZF0008AEAE"
U11: "Digital, triaxial acceleration sensor, 12LGA"
U12: "Buck Step Down Regulator with 3 to 17 V Input and 3.3 V Output, -40 to 85 degC, 8-Pin WSON (DSG), Green (RoHS & no Sb/Br)"
Y1: "Crystal, 16 MHz, 18 pF, SMD"
Y2: "CRYSTAL, 32.768KHZ, 9PF, SMD"
Y3: "Crystal, 40MHz, 8pF, SMD"
ZZ1: library part AssemblyNoteLabel
ZZ2 ZZ3 ZZ4: library part AssemblyNote

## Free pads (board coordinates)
  round 98.43 hole 98.43 unplated mask+10: 1(0,0) 1(0,3849.57) 1(2101.57,0) 1(2101.57,3849.57)

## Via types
v1: diameter 18, hole 8, TOP to BOTTOM, tented both sides, 344 vias
v2: diameter 24, hole 12, TOP to BOTTOM, tented both sides, 244 vias
v3: diameter 24, hole 12.1, TOP to BOTTOM, 36 vias
v4: diameter 30, hole 16, TOP to BOTTOM, tented both sides, 18 vias
v5: diameter 24, hole 12.1, TOP to BOTTOM, tented top, 2 vias

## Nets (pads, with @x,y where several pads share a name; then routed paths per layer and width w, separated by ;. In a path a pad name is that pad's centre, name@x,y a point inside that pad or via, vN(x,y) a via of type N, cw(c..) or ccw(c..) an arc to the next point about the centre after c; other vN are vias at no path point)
ANA_IN1: R68.2 R101.1 R104.1 | length 1007.5
  TOP w8: R68.2@361.41,1449.79 v1(361.41,1482.41)
  TOP w10: R104.1@713.41,2125.79 771.41,2125.79 R101.1@776.79,2131.17 788.79,2119.17 v1(788.79,2093.79)
  PWR w6: v1(361.41,1482.41) 361.41,1602.41 458.79,1699.79 458.79,1786.79 555.79,1883.79 555.79,1921.79 608.79,1974.79 742.79,1974.79 788.79,2020.79 v1(788.79,2093.79)
ANA_IN2: R65.1 R76.2 R108.1 R112.1 | length 1858.9
  TOP w6: R65.1@25.17,1549.79 25.17,1518.17 v1(30.17,1513.17) ; R76.2@356.52,1249.8 410.79,1249.79 437.79,1276.79 v1(437.79,1326.79)
  TOP w8: R108.1@473.79,1904.17 v1(500.17,1877.79) 750.79,1877.79 774.79,1901.79 774.79,1950.79 749.79,1975.79 R112.1@713.41,1975.79
  BOTTOM w6: v1(30.17,1513.17) 30.17,1473.41 101.79,1401.79 303.79,1401.79 378.79,1326.79 v1(437.79,1326.79) 533,1422 533,1500 383,1650 383,1694.28 405.72,1717 450,1717 500.17,1767.17 v1(500.17,1877.79)
ANA_IN3: R79.1 R80.2 R109.1 R113.1 | length 1840.3
  TOP w6: v1(6.17,1190.41) 25.17,1171.41 R79.1@25.17,1150.79 25.17,1116.33 40.71,1100.79 328.59,1100.79 355.12,1127.32 R80.2@355.12,1149.9 ; R109.1@204.17,1909.79 173.79,1909.79 151.79,1931.79 151.79,1987.79 v1(179.79,2015.79) R113.1@216.17,2015.79
  BOTTOM w6: v1(6.17,1190.41) -37.21,1233.79 -37.21,1533.79 27.79,1598.79 287.79,1598.79 298.39,1609.39 311.79,1622.79 311.79,1819.79 222.79,1908.79 222.79,1972.79 v1(179.79,2015.79)
ANA_IN4: R72.2 R100.1 R103.1 | length 1085.1
  TOP w6: R100.1@143.79,2164.17 143.79,2151.79 v1(179.79,2115.79) R103.1@216.17,2115.79 ; R72.2@362.41,1349.79 391.79,1349.79 489.79,1447.79 v1(489.79,1473.79)
  BOTTOM w6: v1(179.79,2115.79) 257.79,2037.79 257.79,1905.79 336.79,1826.79 336.79,1590.79 453.79,1473.79 v1(489.79,1473.79)
CC_NRESET: C27.1 D5.1 J3.10 J8.10 J12.2 R35.2 U7.32 | length 4850.9
  TOP w6: v1(614.79,1854.79) 614.79,1820.79 J12.2@615.79,1819.79 ; U7.32@1168.74,1087.56 1168.74,1044.12 1209.79,1003.07 1209.79,963.17 R35.2@1248.17,924.79 C27.1@1248.17,864.79 1248.17,829.17 v2(1246.79,827.79) ; D5.1@2069.38,1263.79 v1@2100.48,1263.79
  PWR w6: v2(1246.79,827.79) 1304.79,769.79 1611.79,769.79 1651.87,729.7 1714.8,729.7 1780.79,795.69 1780.79,1084.79 1793.79,1097.79 2004.79,1097.79 2102.48,1195.48 v1(2102.48,1263.79) 2102.48,1286.12 2087.81,1300.79 1816.79,1300.79 1789.79,1327.79 1789.79,1523.81 1683.79,1629.81 v1(1683.79,1778.79)
  BOTTOM w6: v1(614.79,1854.79) 761.79,1854.79 839,1932 839,2144.79 ; J3.10@801.79,2414.79 801.79,2202.79 839,2165.58 839,2144.79 ; v1(1683.79,1778.79) 1645.79,1816.79 1645.79,1861.61 1580.61,1926.79 1505.79,1926.79 1417.79,2014.79 1417.79,2146.99 1534.79,2263.99 J8.10@1534.79,2355.79 1461.89,2355.79 1250.89,2144.79 839,2144.79
FL_SWN: L7.1 U7.46 | length 281.2
  TOP w10: U7.46@1194.02,1369.05 1219.51,1369.06 1242.79,1392.33 1242.79,1440.79 1318.45,1516.45 L7.1@1318.45,1583.79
